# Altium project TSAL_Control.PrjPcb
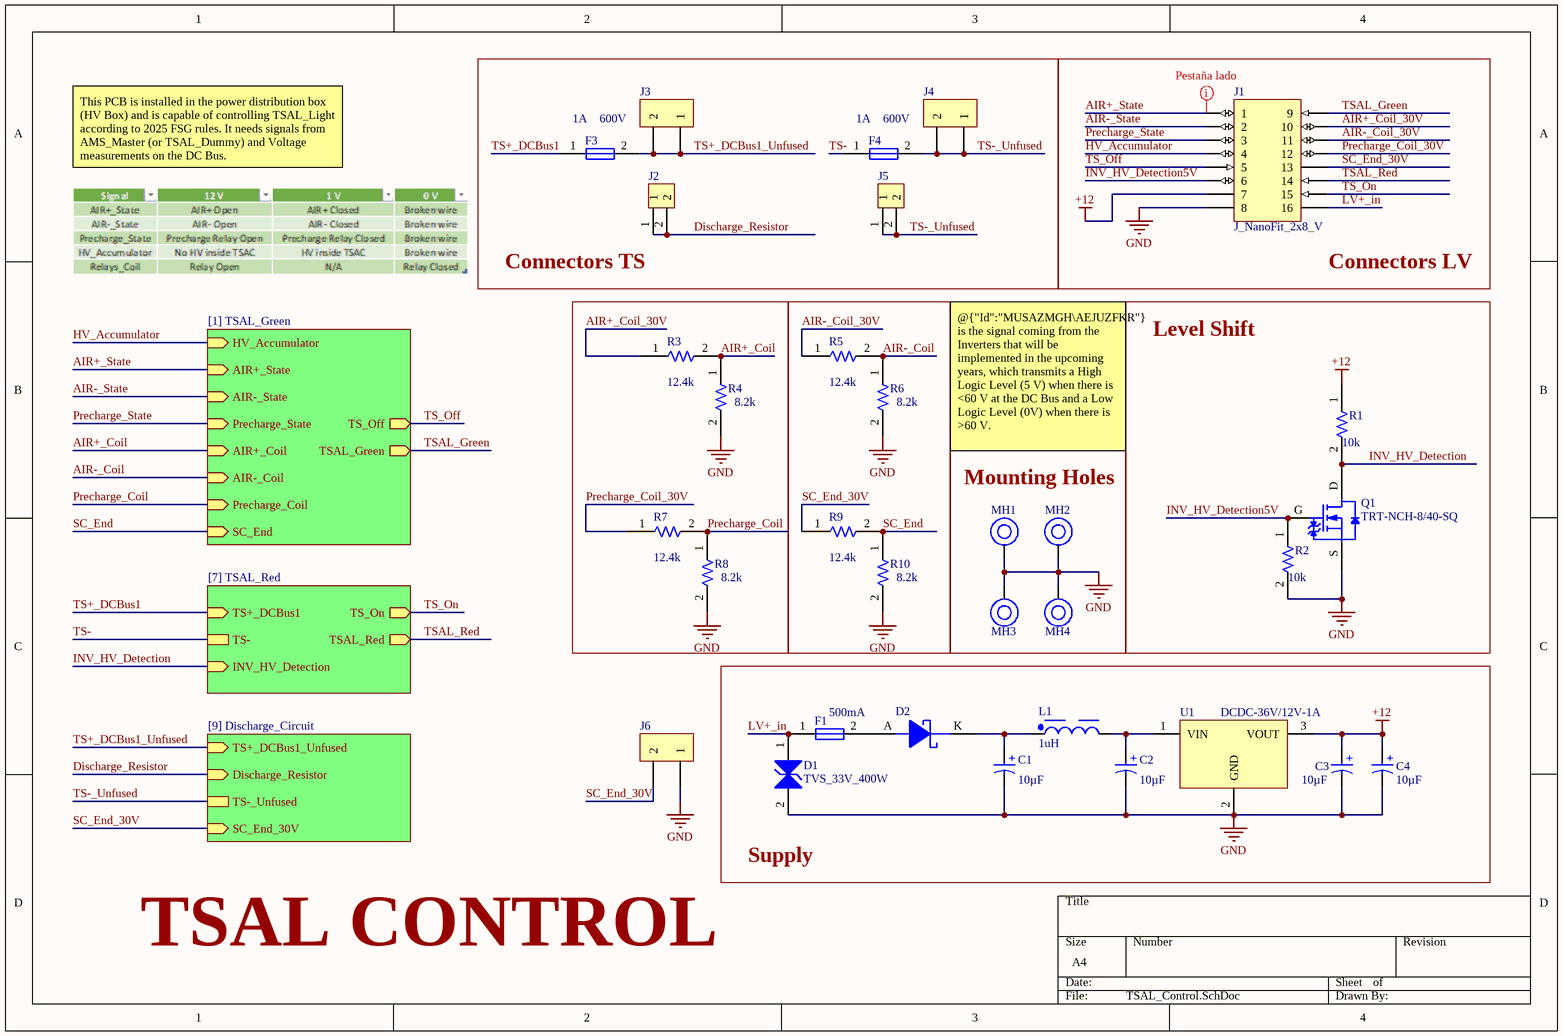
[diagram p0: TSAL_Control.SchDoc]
Company: e-Tech Racing; DesignedbyURL: e-techracing.es; DesignerMail: guillemroper@gmail.com; DesignerName: Guillem Ropero Serrano; Project: TSAL Control
10 sheets, 130 parts. Net scope: hierarchical (ports join the sheet entries above them; power ports are global).
Board file: TSAL_Control.PcbDoc
Sheets:
  TSAL_Control.SchDoc
    TSAL Green = [1] TSAL_Green.SchDoc
      Implausibilities = [2] Implausibilities.SchDoc
        Relay Implausibility = [3] Relay Implausibility.SchDoc
        SCS = [5] SCS.SchDoc
        EV 4.10.14 = [4] NoHV_RelaysClosed.SchDoc
      Green Driver = [6] Green_Driver.SchDoc
    TSAL Red = [7] TSAL_Red.SchDoc
      Red Driver = [8] Red_Driver.SchDoc
    Discharge_circuit = [9] Discharge_Circuit.SchDoc

## Sheet TSAL_Control.SchDoc
size A4; SheetNumber: 1; SheetTotal: 1; SPICEModelCacheMUSAZMGH: <root> / <DocumentId>MUSAZMGH</DocumentId> / </root>

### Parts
C1  value 10µF  [865080540004-Footprint-1]  (hidden comment: C10u-35V-Electrolytic)
C2  value 10µF  [865080540004-Footprint-1]  (hidden comment: C10u-35V-Electrolytic)
C3  value 10µF  [865080540004-Footprint-1]  (hidden comment: C10u-35V-Electrolytic)
C4  value 10µF  [865080540004-Footprint-1]  (hidden comment: C10u-35V-Electrolytic)
D1  TVS_33V_400W  [WE-TVSP_DO-214AC_Bidirectional]
D2  DSC-0.5/30-SOD123  [DSC-SOD123]  (value not drawn)
F1  Current Rating: 500mA  [0805]  (hidden comment: MFU0805FF00500P500)
F3  Current Rating: 1A  Voltage Rating (DC): 600V  [Fuse_485001]  (hidden comment: Fuse_1A_600V)
F4  Current Rating: 1A  Voltage Rating (DC): 600V  [Fuse_485001]  (hidden comment: Fuse_1A_600V)
J1  J_NanoFit_2x8_V  [J_NanoFit_2x8_V]
J2  J_MicroFit_2x1  [J_MicroFit_2x1]  (value not drawn)
J3  J_NanoFit_1x2  [FP-105309-1102-MFG]  (value not drawn)
J4  J_NanoFit_1x2  [FP-105309-1102-MFG]  (value not drawn)
J5  J_MicroFit_2x1  [J_MicroFit_2x1]  (value not drawn)
J6  J_NanoFit_1x2  [FP-105309-1102-MFG]  (value not drawn)
L1  value 1uH  [WE-PD2_4532]  (hidden comment: 7447730)
MH1  Mounting_Hole_M3  [Mounting_Hole_M3]  (value not drawn)
MH2  Mounting_Hole_M3  [Mounting_Hole_M3]  (value not drawn)
MH3  Mounting_Hole_M3  [Mounting_Hole_M3]  (value not drawn)
MH4  Mounting_Hole_M3  [Mounting_Hole_M3]  (value not drawn)
Q1  TRT-NCH-8/40-SQ  [TRT-NCH-3/35-CPH]
R1  value 10k  [R0805FTK]  (hidden comment: R10k-0805FTK)
R2  value 10k  [R0805FTK]  (hidden comment: R10k-0805FTK)
R3  value 12.4k  [0805]  (hidden comment: R12K4-0805-0.125W)
R4  value 8.2k  [0805]  (hidden comment: R8.2K_0805_0.125W)
R5  value 12.4k  [0805]  (hidden comment: R12K4-0805-0.125W)
R6  value 8.2k  [0805]  (hidden comment: R8.2K_0805_0.125W)
R7  value 12.4k  [0805]  (hidden comment: R12K4-0805-0.125W)
R8  value 8.2k  [0805]  (hidden comment: R8.2K_0805_0.125W)
R9  value 12.4k  [0805]  (hidden comment: R12K4-0805-0.125W)
R10  value 8.2k  [0805]  (hidden comment: R8.2K_0805_0.125W)
U1  DCDC-36V/12V-1A  [WPME-FDSM_SIP-3_L11.6W8H10.4]

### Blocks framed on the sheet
Connectors TS: F3 F4 J2-J5
Connectors LV: J1
Level Shift: Q1 R1 R2
Mounting Holes: MH1-MH4
Supply: C1-C4 D1 D2 F1 L1 U1

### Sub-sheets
Discharge_circuit = [9] Discharge_Circuit: Discharge_Resistor (in), SC_End_30V (in), TS-_Unfused, TS+_DCBus1_Unfused (in)
TSAL Green = [1] TSAL_Green: HV_Accumulator (in), AIR+_State (in), Precharge_State (in), AIR+_Coil (in), AIR-_Coil (in), Precharge_Coil (in), SC_End (in), TS_Off (out), TSAL_Green (out), AIR-_State (in)
TSAL Red = [7] TSAL_Red: TS+_DCBus1 (in), TS_On (out), INV_HV_Detection (in), TSAL_Red (out), TS-

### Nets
+12: C3.1(P) C4.1(P) J1.7 R1.1 U1.3(VOUT)
GND: C1.2(N) C2.2(N) C3.2(N) C4.2(N) D1.2 J1.8 J6.1 MH1.1 MH2.1 MH3.1 MH4.1 Q1.S R2.2 R4.2 R6.2 R8.2 R10.2 U1.2(GND)
AIR+_Coil: R3.2 R4.1 ; sheet TSAL Green/AIR+_Coil
AIR+_Coil_30V: J1.10 R3.1
AIR+_State: J1.1 ; sheet TSAL Green/AIR+_State
AIR-_Coil: R5.2 R6.1 ; sheet TSAL Green/AIR-_Coil
AIR-_Coil_30V: J1.11 R5.1
AIR-_State: J1.2 ; sheet TSAL Green/AIR-_State
Discharge_Resistor: J2.1 J2.2 ; sheet Discharge_circuit/Discharge_Resistor
HV_Accumulator: J1.4 ; sheet TSAL Green/HV_Accumulator
INV_HV_Detection: Q1.D R1.2 ; sheet TSAL Red/INV_HV_Detection
INV_HV_Detection5V: J1.6 Q1.G R2.1
LV+_in: D1.1 F1.1 J1.16
Precharge_Coil: R7.2 R8.1 ; sheet TSAL Green/Precharge_Coil
Precharge_Coil_30V: J1.12 R7.1
Precharge_State: J1.3 ; sheet TSAL Green/Precharge_State
SC_End: R9.2 R10.1 ; sheet TSAL Green/SC_End
SC_End_30V: J1.13 J6.2 R9.1 ; sheet Discharge_circuit/SC_End_30V
TS+_DCBus1: F3.1 ; sheet TSAL Red/TS+_DCBus1
TS+_DCBus1_Unfused: F3.2 J3.1 J3.2 ; sheet Discharge_circuit/TS+_DCBus1_Unfused
TS-: F4.1 ; sheet TSAL Red/TS-
TS-_Unfused: F4.2 J4.1 J4.2 J5.1 J5.2 ; sheet Discharge_circuit/TS-_Unfused
TS_Off: J1.5 ; sheet TSAL Green/TS_Off
TS_On: J1.15 ; sheet TSAL Red/TS_On
TSAL_Green: J1.9 ; sheet TSAL Green/TSAL_Green
TSAL_Red: J1.14 ; sheet TSAL Red/TSAL_Red
NetC1_1: C1.1(P) D2.K L1.1
NetC2_1: C2.1(P) L1.2 U1.1(VIN)
NetD2_A: D2.A F1.2

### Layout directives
mark named Pestaña lado: AIR+_State

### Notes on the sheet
- This PCB is installed in the power distribution box (HV Box) and is capable of controlling TSAL_Light according to 2025 FSG rules. It needs signals from AMS_Master (or TSAL_Dummy) and Voltage measurements on the DC Bus.
- @{"Id":"MUSAZMGH\AEJUZFKR"} is the signal coming from the Inverters that will be implemented in the upcoming years, which transmits a High Logic Level (5 V) when there is <60 V at the DC Bus and a Low Logic Level (0V) when there is >60 V.
- TSAL CONTROL

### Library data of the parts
C1-C4 = CMP-001-00019-3: WCAP-ASLI Aluminum Electrolytic Capacitors; Tolerance: 20%; Ripple Current (AC): 90mA; Voltage Rating: 35V
D1 = CMP-004-00003-1: Trans Voltage Suppressor Diode, 400W, Bidirectional, 1 Element, Silicon, DO-214AC
D2 = CMP-00165-2: VR=30V IF=500mA 30pF P=410mW; Max Reverse Leakage Current: 130uA; .Creator: GP; Max Reverse Voltage (DC): 30V; Element Configuration: Single; Average Rectified Current: 500mA; Peak Non-Repetitive Surge Current: 5.5A; Polarity: Standard; Forward Voltage: 430mV
F1 = CMP-001-00020-3: Fuse, 24 Milliohms to 660 Milliohms (Cold) @ 0.1, 32 V, 0805, 15 C, 35 C; Value: 0.5A-50V
F3 F4 = CMP-00161-2: Surface Mount Fuses 600V 1A Fast Acting; Manufacturer Part Number 1: 0485001.DR; Manufacturer 1: Littelfuse; .Creator: DO; Voltage Rating (AC): 250V; Approvals: UL,CSA; Fuse Type: Board Mount (Cartridge Style Excluded); Resistance: 0.264; DC Cold Resistance: 304.4mR; Body Material: Ceramic
J1 = CMP-00020-3: Nano-Fit Vertical Header Through Hole 2.50mm Pitch Dual Row 16 Circuits with Kinked Pins Tin (Sn) Plating Black; Manufacturer 1: Molex; Manufacturer Part Number 1: 105310-1116; Connector Type: Header,Male Pin; Number of Positions: 16; .Creator: AC
J2 J5 = CMP-00012-1: Header 1 Row Vertical Polarizing Peg 2 Pin SMT/Glow Wire Compatible Tin Plate; Manufacturer 1: Molex; Manufacturer Part Number 1: 43650-0215
J3 J4 J6 = CMP-002-00001-2: Conn HDR 2 POS 2.5mm Solder ST Thru-Hole 2 Terminal 1 Port Nano-Fit Tray
L1 = CMP-006-00005-1: General Purpose Inductor, 1uH, 20%, 1 Element, Nickel-zinc Ferrite-Core, SMD, 1816; Self Resonant Frequency: 110MHz; Max Current Rating: 4A
MH1-MH4 = CMP-00040-2
Q1 = CMP-00142-1: Automotive N-channel 40 V (d-s) 175C Mosfet SOT-23; Manufacturer Part Number 1: SQ2318BES-T1_GE3; Manufacturer 1: Vishay; Vds: 40V; .Creator: DO
R1 R2 = CMP-00085-4: BOURNS         CR0805-JW-103ELF            Surface Mount Chip Resistor, Thick Film, CR Series, 10 kohm, 125 mW,  5%, 150 V; Voltage Rating: 150V; Voltage Rating (DC): 100V; Max Power Dissipation: 125mW; Temperature Coefficient: 200ppm/°C; .Creator: DR
R3 R5 R7 R9 = CMP-009-00046-1: Fixed Resistor, Metal Glaze/thick Film, 0.125W, 12400ohm, 150V, 1% +/-Tol, 100ppm/Cel, Surface Mount, 0805; Power: 125mW
R4 R6 R8 R10 = CMP-009-00044-2: Fixed Resistor, Metal Glaze/thick Film, 0.125W, 8200ohm, 150V, 1% +/-Tol, 100ppm/Cel, Surface Mount, 0805; Power: 125mW
U1 = CMP-019-00006-1: Switching Regulator 36V In / 12 V Out, 1A. 173011235

## Sheet [1] TSAL_Green.SchDoc
size A4
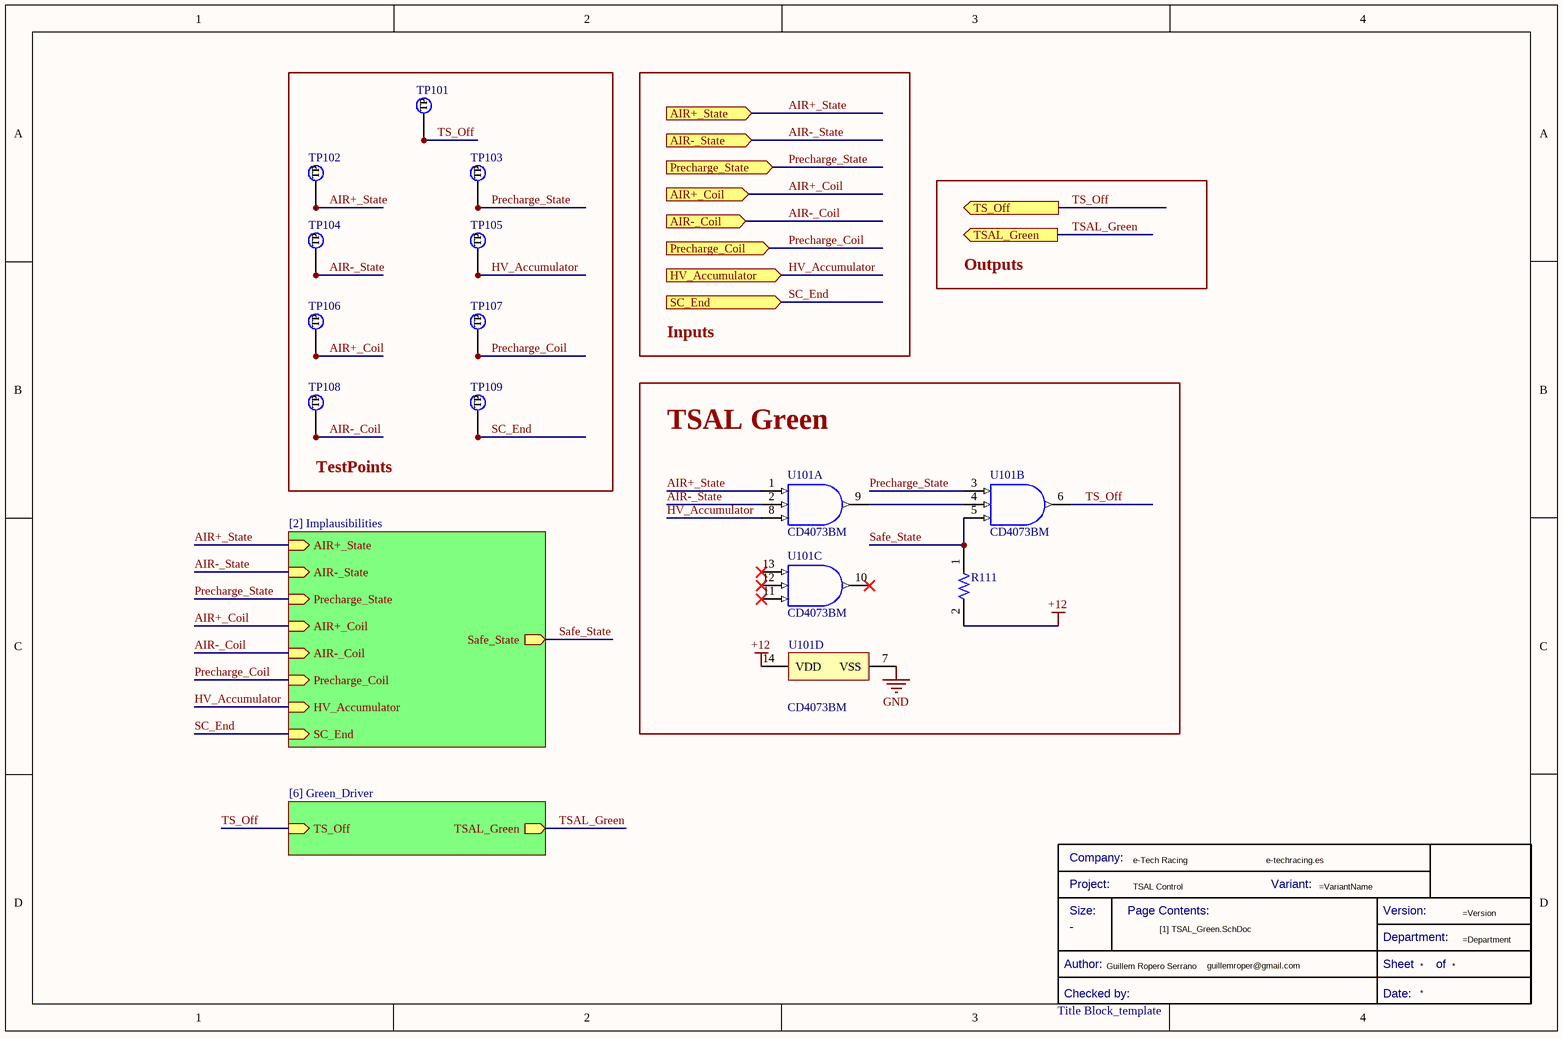
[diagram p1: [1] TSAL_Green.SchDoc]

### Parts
(Parts that share a designator on the sheet are numbered #1, #2 ... from top to bottom, then left to right.)
*#1  Title Block_template  (graphical)
R111  R470-0805FTK  [R0805FTK]  (value not drawn)
TP101  TestPoint  [TestPoint]  (value not drawn)  (no BOM)
TP102  TestPoint  [TestPoint]  (value not drawn)  (no BOM)
TP103  TestPoint  [TestPoint]  (value not drawn)  (no BOM)
TP104  TestPoint  [TestPoint]  (value not drawn)  (no BOM)
TP105  TestPoint  [TestPoint]  (value not drawn)  (no BOM)
TP106  TestPoint  [TestPoint]  (value not drawn)  (no BOM)
TP107  TestPoint  [TestPoint]  (value not drawn)  (no BOM)
TP108  TestPoint  [TestPoint]  (value not drawn)  (no BOM)
TP109  TestPoint  [TestPoint]  (value not drawn)  (no BOM)
U101  CD4073BM  [D0014A_N]  (parts A,B,C,D of 4)

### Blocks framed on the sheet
TestPoints: TP101-TP109
TSAL Green: R111 U101

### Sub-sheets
Green Driver = [6] Green_Driver: TS_Off (in), TSAL_Green (out)
Implausibilities = [2] Implausibilities: AIR+_State (in), Precharge_State (in), AIR+_Coil (in), AIR-_Coil (in), Precharge_Coil (in), HV_Accumulator (in), Safe_State (out), SC_End (in), AIR-_State (in)

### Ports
AIR+_Coil (in, see TSAL_Control[1B], [2] Implausibilities[1A], [3] Relay Implausibility[1A], [4] NoHV_RelaysClosed[1A]), AIR+_State (in, see TSAL_Control[1B], [2] Implausibilities[1A], [3] Relay Implausibility[1A], [5] SCS[1A]), AIR-_Coil (in, see TSAL_Control[1B], [2] Implausibilities[1A], [3] Relay Implausibility[1A], [4] NoHV_RelaysClosed[1A]), AIR-_State (in, see TSAL_Control[1B], [2] Implausibilities[1A], [3] Relay Implausibility[1A], [5] SCS[1A]), HV_Accumulator (in, see TSAL_Control[1B], [2] Implausibilities[1A], [4] NoHV_RelaysClosed[1A], [5] SCS[1A]), Precharge_Coil (in, see TSAL_Control[1C], [2] Implausibilities[1A], [3] Relay Implausibility[1A], [4] NoHV_RelaysClosed[1A]), Precharge_State (in, see TSAL_Control[1B], [2] Implausibilities[1A], [3] Relay Implausibility[1A], [5] SCS[1A]), SC_End (in, see TSAL_Control[1C], [2] Implausibilities[1A], [3] Relay Implausibility[1B], [4] NoHV_RelaysClosed[1A]), TS_Off (out, see TSAL_Control[2B], [6] Green_Driver[1A]), TSAL_Green (out, see TSAL_Control[2B], [6] Green_Driver[2A])

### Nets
+12: R111.2 U101.14(VDD)
GND: U101.7(VSS)
AIR+_Coil: TP106.1(TP) ; port AIR+_Coil, sheet Implausibilities/AIR+_Coil
AIR+_State: TP102.1(TP) U101.1(A) ; port AIR+_State, sheet Implausibilities/AIR+_State
AIR-_Coil: TP108.1(TP) ; port AIR-_Coil, sheet Implausibilities/AIR-_Coil
AIR-_State: TP104.1(TP) U101.2(B) ; port AIR-_State, sheet Implausibilities/AIR-_State
HV_Accumulator: TP105.1(TP) U101.8(C) ; port HV_Accumulator, sheet Implausibilities/HV_Accumulator
Precharge_Coil: TP107.1(TP) ; port Precharge_Coil, sheet Implausibilities/Precharge_Coil
Precharge_State: TP103.1(TP) U101.3(D) ; port Precharge_State, sheet Implausibilities/Precharge_State
Safe_State: R111.1 U101.5(F) ; sheet Implausibilities/Safe_State
SC_End: TP109.1(TP) ; port SC_End, sheet Implausibilities/SC_End
TS_Off: TP101.1(TP) U101.6(K) ; port TS_Off, sheet Green Driver/TS_Off
TSAL_Green: port TSAL_Green, sheet Green Driver/TSAL_Green
NetU101_4: U101.4(E) U101.9(J)

Not connected (* = marked no-connect by the designer): U101 10(L)* 11(I)* 12(H)* 13(G)*

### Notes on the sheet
- Outputs
- Inputs

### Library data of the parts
*#1 = CMP-00043-7: Standard Title Block; .Creator: GP
R111 = CMP-00093-2: Res Thick Film 0805 470 Ohm 1% 1/8W ±100ppm/°C Molded SMD SMD Paper Tape on Plastic Reel; Manufacturer Part Number 1: CR0805-FX-4700GLF; Manufacturer 1: Bourns; Power Rating: 125mW; Voltage Rating (DC): 150V; .Creator: DR; Value: 470
TP101-TP109 = CMP-00042-1: Test Point 1x1 mm; .SCHcheck: GP
U101 = CMP-00213-1: AND Gate, 4000/14000/40000 Series, 3-Func, 3-Input, CMOS, PDSO14; Propagation Delay (tpd): 250ns; Nominal Supply Voltage: 5V; Power Supplies: 5/15V; Qualification Status: Not Qualified; Package Equivalence Code: SOP14,.25; Channels: 3; Min Supply Voltage: 3V; Package Body Material: Plastic; Max Supply Voltage: 18V; Load Capacitance (CL): 50pF; Load/Preset Input: Yes; Schmitt Trigger: No

## Sheet [2] Implausibilities.SchDoc
size A4
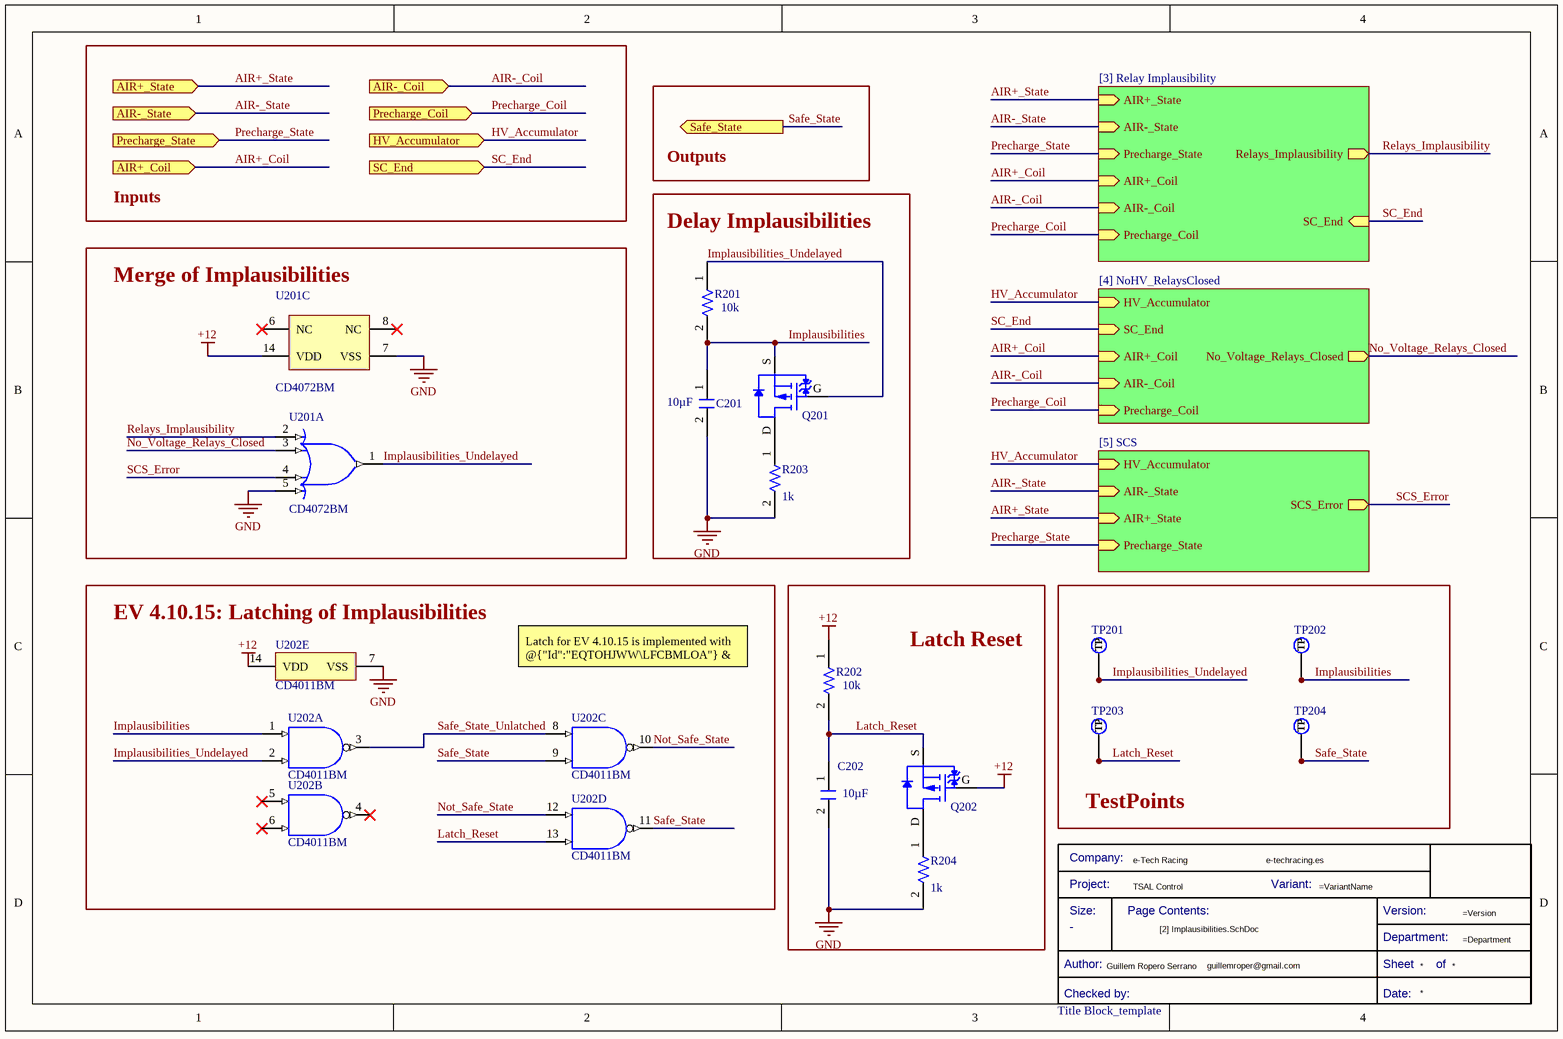
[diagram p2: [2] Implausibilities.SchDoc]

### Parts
(Parts that share a designator on the sheet are numbered #1, #2 ... from top to bottom, then left to right.)
*#2  Title Block_template  (graphical)
C201  value 10µF  [C0805FNPC-R]  (hidden comment: C10u-16V-0805FNPC-X5R)
C202  value 10µF  [C0805FNPC-R]  (hidden comment: C10u-16V-0805FNPC-X5R)
Q201  TRT-PCH-2/30-BSS  [TRT-PCH-2/30-BSS]  (value not drawn)
Q202  TRT-PCH-2/30-BSS  [TRT-PCH-2/30-BSS]  (value not drawn)
R201  value 10k  [R0805FTK]  (hidden comment: R10k-0805FTK)
R202  value 10k  [R0805FTK]  (hidden comment: R10k-0805FTK)
R203  value 1k  [0805]  (hidden comment: R1K-0805-0.5W)
R204  value 1k  [0805]  (hidden comment: R1K-0805-0.5W)
TP201  TestPoint  [TestPoint]  (value not drawn)  (no BOM)
TP202  TestPoint  [TestPoint]  (value not drawn)  (no BOM)
TP203  TestPoint  [TestPoint]  (value not drawn)  (no BOM)
TP204  TestPoint  [TestPoint]  (value not drawn)  (no BOM)
U201  CD4072BM  [D0014A_N]  (parts A,C of 3)
U202  CD4011BM  [D0014A_N]  (parts A,B,C,D,E of 5)

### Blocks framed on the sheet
Delay Implausibilities: C201 Q201 R201 R203
Merge of Implausibilities: U201
EV 4.10.15: Latching of Implausibilities: U202
Latch Reset: C202 Q202 R202 R204
TestPoints: TP201-TP204

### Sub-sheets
EV 4.10.14 = [4] NoHV_RelaysClosed: HV_Accumulator (in), SC_End (in), AIR+_Coil (in), AIR-_Coil (in), Precharge_Coil (in), No_Voltage_Relays_Closed (out)
Relay Implausibility = [3] Relay Implausibility: AIR+_State (in), Precharge_State (in), AIR+_Coil (in), AIR-_Coil (in), Precharge_Coil (in), Relays_Implausibility (out), SC_End (in), AIR-_State (in)
SCS = [5] SCS: HV_Accumulator (in), AIR-_State (in), Precharge_State (in), SCS_Error (out), AIR+_State (in)

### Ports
AIR+_Coil (in, see [1] TSAL_Green[1C], [1] TSAL_Green[2A], [3] Relay Implausibility[1A], [4] NoHV_RelaysClosed[1A]), AIR+_State (in, see [1] TSAL_Green[1C], [1] TSAL_Green[2A], [3] Relay Implausibility[1A], [5] SCS[1A]), AIR-_Coil (in, see [1] TSAL_Green[1C], [1] TSAL_Green[2A], [3] Relay Implausibility[1A], [4] NoHV_RelaysClosed[1A]), AIR-_State (in, see [1] TSAL_Green[1C], [1] TSAL_Green[2A], [3] Relay Implausibility[1A], [5] SCS[1A]), HV_Accumulator (in, see [1] TSAL_Green[1C], [1] TSAL_Green[2B], [4] NoHV_RelaysClosed[1A], [5] SCS[1A]), Precharge_Coil (in, see [1] TSAL_Green[1C], [1] TSAL_Green[2A], [3] Relay Implausibility[1A], [4] NoHV_RelaysClosed[1A]), Precharge_State (in, see [1] TSAL_Green[1C], [1] TSAL_Green[2A], [3] Relay Implausibility[1A], [5] SCS[1A]), Safe_State (out, see [1] TSAL_Green[2C]), SC_End (in, see [1] TSAL_Green[1C], [1] TSAL_Green[2B], [3] Relay Implausibility[1B], [4] NoHV_RelaysClosed[1A])

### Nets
+12: Q202.G R202.1 U201.14(VDD) U202.14(VDD)
GND: C201.2 C202.2 R203.2 R204.2 U201.5(D) U201.7(VSS) U202.7(VSS)
AIR+_Coil: port AIR+_Coil, sheet Relay Implausibility/AIR+_Coil, sheet EV 4.10.14/AIR+_Coil
AIR+_State: port AIR+_State, sheet Relay Implausibility/AIR+_State, sheet SCS/AIR+_State
AIR-_Coil: port AIR-_Coil, sheet Relay Implausibility/AIR-_Coil, sheet EV 4.10.14/AIR-_Coil
AIR-_State: port AIR-_State, sheet Relay Implausibility/AIR-_State, sheet SCS/AIR-_State
HV_Accumulator: port HV_Accumulator, sheet SCS/HV_Accumulator, sheet EV 4.10.14/HV_Accumulator
Implausibilities: C201.1 Q201.S R201.2 TP202.1(TP) U202.1(A)
Implausibilities_Undelayed: Q201.G R201.1 TP201.1(TP) U201.1(J) U202.2(B)
Latch_Reset: C202.1 Q202.S R202.2 TP203.1(TP) U202.13(H)
No_Voltage_Relays_Closed: U201.3(B) ; sheet EV 4.10.14/No_Voltage_Relays_Closed
Not_Safe_State: U202.10(L) U202.12(G)
Precharge_Coil: port Precharge_Coil, sheet Relay Implausibility/Precharge_Coil, sheet EV 4.10.14/Precharge_Coil
Precharge_State: port Precharge_State, sheet Relay Implausibility/Precharge_State, sheet SCS/Precharge_State
Relays_Implausibility: U201.2(A) ; sheet Relay Implausibility/Relays_Implausibility
Safe_State: TP204.1(TP) U202.9(F) U202.11(M) ; port Safe_State
Safe_State_Unlatched: U202.3(J) U202.8(E)
SC_End: port SC_End, sheet Relay Implausibility/SC_End, sheet EV 4.10.14/SC_End
SCS_Error: U201.4(C) ; sheet SCS/SCS_Error
NetQ201_D: Q201.D R203.1
NetQ202_D: Q202.D R204.1

Not connected (* = marked no-connect by the designer): U201 6(NC)* 8(NC)*; U202 4(K)* 5(C)* 6(D)*

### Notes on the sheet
- Outputs
- Inputs
- Latch for EV 4.10.15 is implemented with @{"Id":"EQTOHJWW\LFCBMLOA"} & @{"Id":"EQTOHJWW\TXFEAGDM"}

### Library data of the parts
*#2 = CMP-00043-7: Standard Title Block; .Creator: GP
C201 C202 = CMP-00055-8: Multilayer Ceramic Capacitor, Wcap-Csgp Series, 10 F, 20%, X5R, 16 V, 0805 [2012 Metric] Rohs Compliant: Yes; Manufacturer Part Number 1: 885012107014; Manufacturer 1: Wurth Electronics; .Creator: DR; Voltage Rating: 16V
Q201 Q202 = CMP-00144-2: Infineon’s highly innovative OptiMOS™ families include p-channel power MOSFETs, SOT-23-3, RoHS; Manufacturer Part Number: BSS308PEH6327; .Creator: DO; Drain to Source Voltage (Vdss): 30V; Rise Time: 7.7ns; Turn-On Delay Time: 5.6ns; Fall Time: 2.8ns; Input Capacitance: 500pF; Turn-Off Delay Time: 15.3ns; Rds On Max: 80mR; Threshold Voltage: -1.5V; Gate to Source Voltage (Vgs): 20V; Max Power Dissipation: 500mW; Continuous Drain Current (ID): 2A
R201 R202 = CMP-00085-4: BOURNS         CR0805-JW-103ELF            Surface Mount Chip Resistor, Thick Film, CR Series, 10 kohm, 125 mW,  5%, 150 V; .Creator: DR; Power Rating: 125mW; Voltage Rating (DC): 100V; Voltage Rating: 150V; Temperature Coefficient: 200ppm/°C
R203 R204 = CMP-009-00043-2: Fixed Resistor, Metal Glaze/thick Film, 0.5W, 1000ohm, 150V, 1% +/-Tol, 100ppm/Cel, Surface Mount, 0805; Power: 500mW
TP201-TP204 = CMP-00042-1: Test Point 1x1 mm; .SCHcheck: GP
U201 = CMP-00217-1: OR Gate, 4000/14000/40000 Series, 2-Func, 4-Input, CMOS, PDSO14; Package Equivalence Code: SOP14,.25; Package Body Material: Plastic; Power Supplies: 5/15V; Schmitt Trigger: No; Propagation Delay (tpd): 250ns; Nominal Supply Voltage: 5V; Min Supply Voltage: 3V; Channels: 2; Output Characteristics: OPEN-COLLECTOR; Max Supply Voltage: 18V; Load Capacitance (CL): 50pF; Logic Type: OR GATE; Qualification Status: Not Qualified; Number of Inputs: 4
U202 = CMP-00211-1: NAND Gate, 4000/14000/40000 Series, 4-Func, 2-Input, CMOS, PDSO14; Package Equivalence Code: SOP14,.25; Package Body Material: Plastic; Load Capacitance (CL): 50pF; Max Supply Voltage: 18V; Min Supply Voltage: 3V; Nominal Supply Voltage: 5V; Propagation Delay (tpd): 250ns; Number of Inputs: 2; Channels: 4; Qualification Status: Not Qualified; Load/Preset Input: Yes; Schmitt Trigger: No; Power Supplies: 5/15V

## Sheet [3] Relay Implausibility.SchDoc
size A4
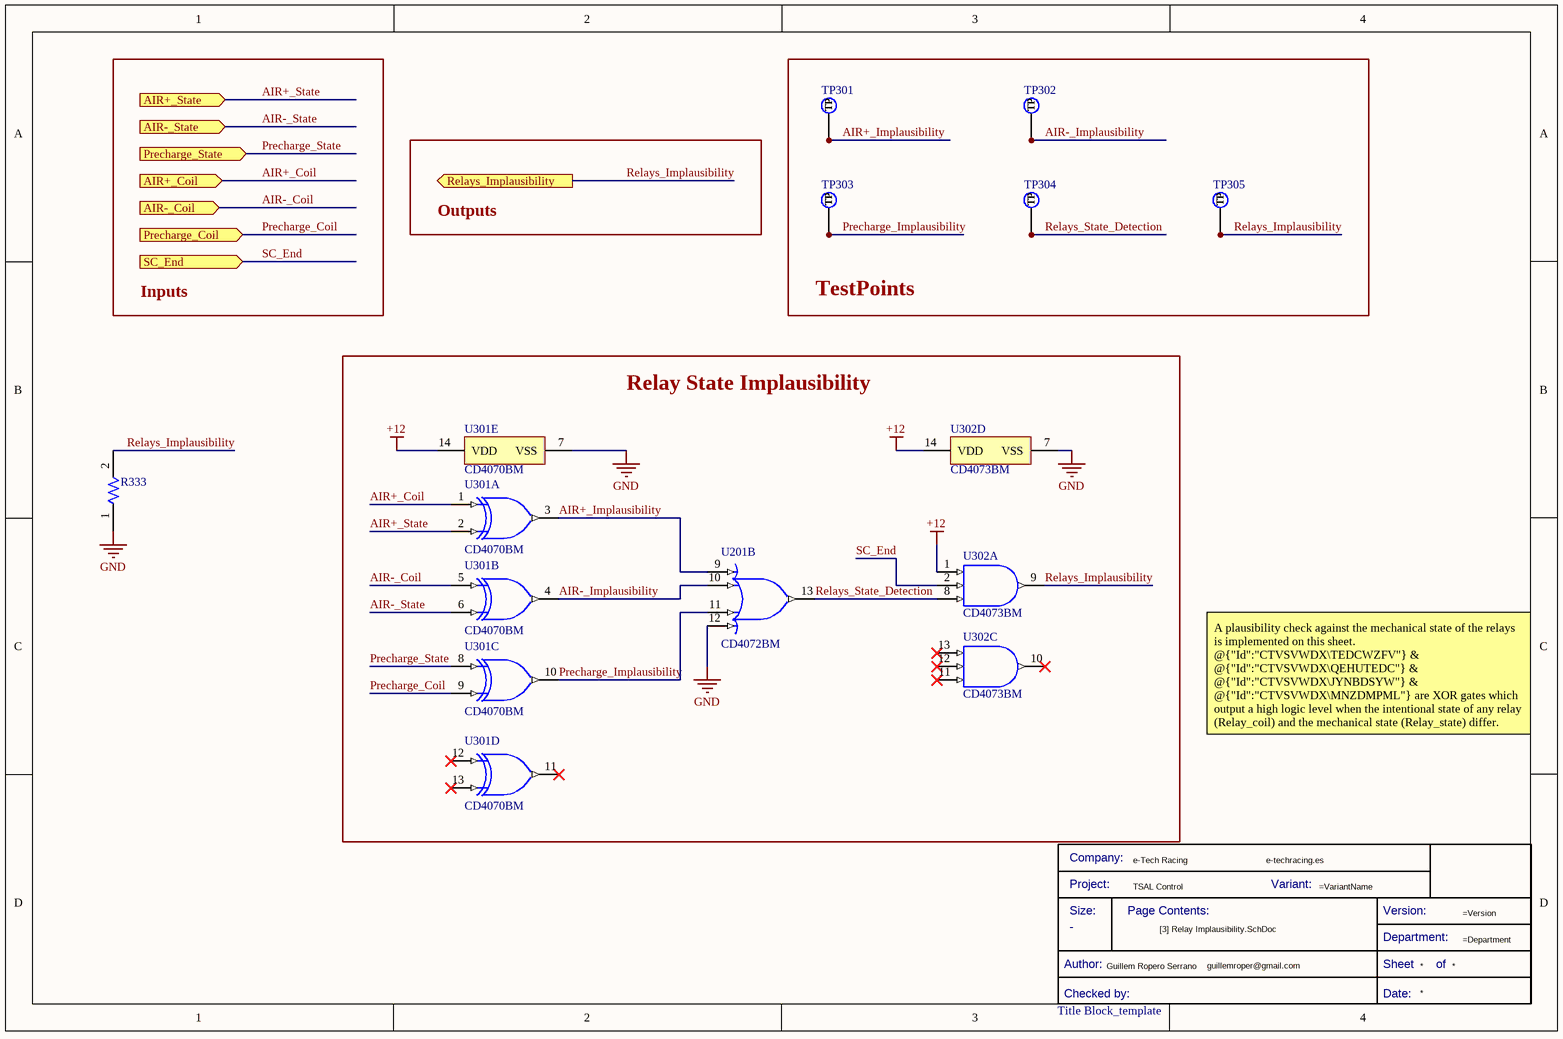
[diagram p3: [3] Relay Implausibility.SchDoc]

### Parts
(Parts that share a designator on the sheet are numbered #1, #2 ... from top to bottom, then left to right.)
*#3  Title Block_template  (graphical)
R333  R470-0805FTK  [R0805FTK]  (value not drawn)
TP301  TestPoint  [TestPoint]  (value not drawn)  (no BOM)
TP302  TestPoint  [TestPoint]  (value not drawn)  (no BOM)
TP303  TestPoint  [TestPoint]  (value not drawn)  (no BOM)
TP304  TestPoint  [TestPoint]  (value not drawn)  (no BOM)
TP305  TestPoint  [TestPoint]  (value not drawn)  (no BOM)
U201  CD4072BM  [D0014A_N]  (part B of 3)
U301  CD4070BM  [D0014A_N]  (parts A,B,C,D,E of 5)
U302  CD4073BM  [D0014A_N]  (parts A,C,D of 4)

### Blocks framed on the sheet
TestPoints: TP301-TP305
Relay State Implausibility: U201 U301 U302

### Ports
AIR+_Coil (in, see [2] Implausibilities[3A], [1] TSAL_Green[2A], [2] Implausibilities[1A], [4] NoHV_RelaysClosed[1A]), AIR+_State (in, see [2] Implausibilities[3A], [1] TSAL_Green[2A], [2] Implausibilities[1A], [5] SCS[1A]), AIR-_Coil (in, see [2] Implausibilities[3A], [1] TSAL_Green[2A], [2] Implausibilities[1A], [4] NoHV_RelaysClosed[1A]), AIR-_State (in, see [2] Implausibilities[3A], [1] TSAL_Green[2A], [2] Implausibilities[1A], [5] SCS[1A]), Precharge_Coil (in, see [2] Implausibilities[3A], [1] TSAL_Green[2A], [2] Implausibilities[1A], [4] NoHV_RelaysClosed[1A]), Precharge_State (in, see [2] Implausibilities[3A], [1] TSAL_Green[2A], [2] Implausibilities[1A], [5] SCS[1A]), Relays_Implausibility (out, see [2] Implausibilities[4A]), SC_End (in, see [2] Implausibilities[4A], [1] TSAL_Green[2B], [2] Implausibilities[1A], [4] NoHV_RelaysClosed[1A])

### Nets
+12: U301.14(VDD) U302.1(A) U302.14(VDD)
GND: R333.1 U201.12(H) U301.7(VSS) U302.7(VSS)
AIR+_Coil: U301.1(A) ; port AIR+_Coil
AIR+_Implausibility: TP301.1(TP) U201.9(E) U301.3(J)
AIR+_State: U301.2(B) ; port AIR+_State
AIR-_Coil: U301.5(C) ; port AIR-_Coil
AIR-_Implausibility: TP302.1(TP) U201.10(F) U301.4(K)
AIR-_State: U301.6(D) ; port AIR-_State
Precharge_Coil: U301.9(F) ; port Precharge_Coil
Precharge_Implausibility: TP303.1(TP) U201.11(G) U301.10(L)
Precharge_State: U301.8(E) ; port Precharge_State
Relays_Implausibility: R333.2 TP305.1(TP) U302.9(J) ; port Relays_Implausibility
Relays_State_Detection: TP304.1(TP) U201.13(K) U302.8(C)
SC_End: U302.2(B) ; port SC_End

Not connected (* = marked no-connect by the designer): U301 11(M)* 12(G)* 13(H)*; U302 10(L)* 11(I)* 12(H)* 13(G)*

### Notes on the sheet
- Outputs
- Inputs
- A plausibility check against the mechanical state of the relays is implemented on this sheet. @{"Id":"CTVSVWDX\TEDCWZFV"} & @{"Id":"CTVSVWDX\QEHUTEDC"} & @{"Id":"CTVSVWDX\JYNBDSYW"} & @{"Id":"CTVSVWDX\MNZDMPML"} are XOR gates which output a high logic level when the intentional state of any relay (Relay_coil) and the mechanical state (Relay_state) differ.
  As the Relay's Coil inside the TSAC are supplied directly from the Shutdown Chain, the @{"Id":"CTVSVWDX\UYTFIWRP"} conditions the implausibility detection to the SC to be closed.

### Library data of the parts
*#3 = CMP-00043-7: Standard Title Block; .Creator: GP
R333 = CMP-00093-2: as R111 on sheet [1] TSAL_Green
TP301-TP305 = CMP-00042-1: Test Point 1x1 mm; .SCHcheck: GP
U201 = CMP-00217-1: as U201 on sheet [2] Implausibilities
U301 = CMP-00216-1: XOR Gate, 4000/14000/40000 Series, 4-Func, 2-Input, CMOS, PDSO14; Package Equivalence Code: SOP14,.25; Number of Inputs: 2; Nominal Supply Voltage: 5V; Qualification Status: Not Qualified; Max Supply Voltage: 18V; Channels: 4; Min Supply Voltage: 3V; Prop. Delay@Nom-Sup: 280ns; Package Body Material: Plastic; Schmitt Trigger: No; Load Capacitance (CL): 50pF; Power Supplies: 5/15V
U302 = CMP-00213-1: as U101 on sheet [1] TSAL_Green

## Sheet [5] SCS.SchDoc
size A4
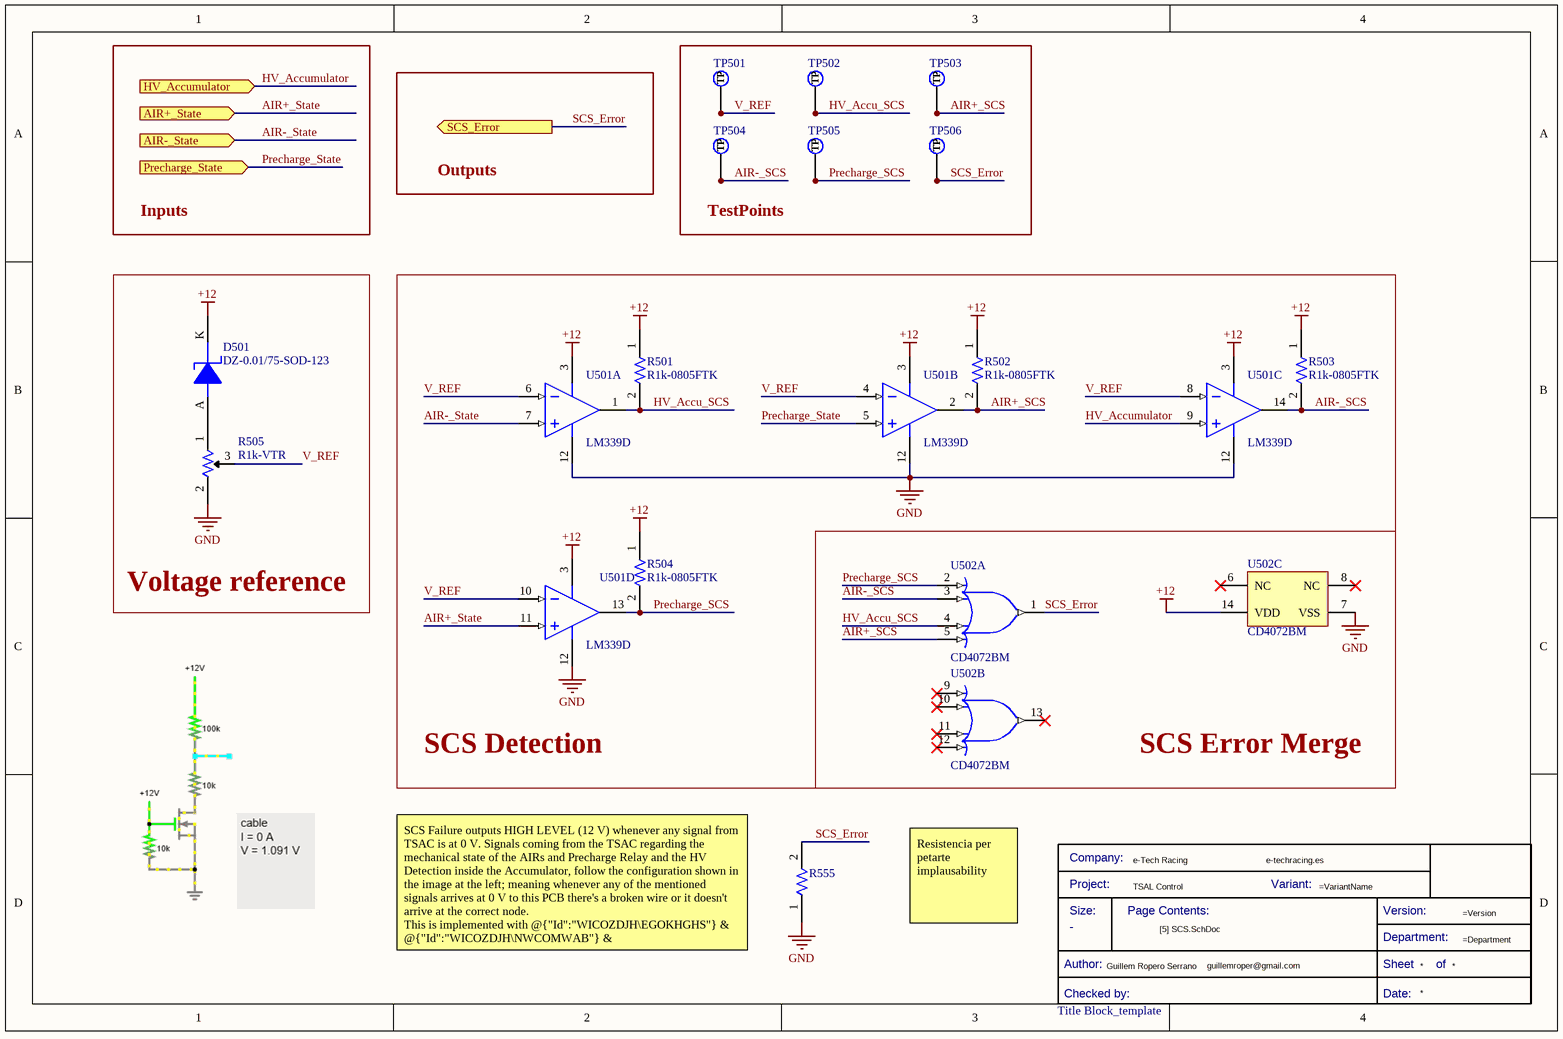
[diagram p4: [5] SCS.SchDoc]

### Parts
(Parts that share a designator on the sheet are numbered #1, #2 ... from top to bottom, then left to right.)
*#4  Title Block_template  (graphical)
D501  DZ-0.01/75-SOD-123  [DSC-SOD123]
R501  R1k-0805FTK  [R0805FTK]
R502  R1k-0805FTK  [R0805FTK]
R503  R1k-0805FTK  [R0805FTK]
R504  R1k-0805FTK  [R0805FTK]
R505  R1k-VTR  [R1k-VTR]
R555  R470-0805FTK  [R0805FTK]  (value not drawn)
TP501  TestPoint  [TestPoint]  (value not drawn)  (no BOM)
TP502  TestPoint  [TestPoint]  (value not drawn)  (no BOM)
TP503  TestPoint  [TestPoint]  (value not drawn)  (no BOM)
TP504  TestPoint  [TestPoint]  (value not drawn)  (no BOM)
TP505  TestPoint  [TestPoint]  (value not drawn)  (no BOM)
TP506  TestPoint  [TestPoint]  (value not drawn)  (no BOM)
U501  LM339D  [D0014A_N]  (parts A,B,C,D of 4)
U502  CD4072BM  [D0014A_N]  (parts A,B,C of 3)

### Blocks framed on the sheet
TestPoints: TP501-TP506
Voltage reference: D501 R505
SCS Detection: R501-R504 U501
SCS Error Merge: U502

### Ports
AIR+_State (in, see [2] Implausibilities[3C], [1] TSAL_Green[2A], [2] Implausibilities[1A], [3] Relay Implausibility[1A]), AIR-_State (in, see [2] Implausibilities[3B], [1] TSAL_Green[2A], [2] Implausibilities[1A], [3] Relay Implausibility[1A]), HV_Accumulator (in, see [2] Implausibilities[3B], [1] TSAL_Green[2B], [2] Implausibilities[1A], [4] NoHV_RelaysClosed[1A]), Precharge_State (in, see [2] Implausibilities[3C], [1] TSAL_Green[2A], [2] Implausibilities[1A], [3] Relay Implausibility[1A]), SCS_Error (out, see [2] Implausibilities[4B])

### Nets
+12: D501.K R501.1 R502.1 R503.1 R504.1 U501.3(VCC) U502.14(VDD)
GND: R505.2 R555.1 U501.12(GND) U502.7(VSS)
AIR+_SCS: R502.2 TP503.1(TP) U501.2(OUT2) U502.5(D)
AIR+_State: U501.11(IN4+) ; port AIR+_State
AIR-_SCS: R503.2 TP504.1(TP) U501.14(OUT3) U502.3(B)
AIR-_State: U501.7(IN1+) ; port AIR-_State
HV_Accu_SCS: R501.2 TP502.1(TP) U501.1(OUT1) U502.4(C)
HV_Accumulator: U501.9(IN3+) ; port HV_Accumulator
Precharge_SCS: R504.2 TP505.1(TP) U501.13(OUT4) U502.2(A)
Precharge_State: U501.5(IN2+) ; port Precharge_State
SCS_Error: R555.2 TP506.1(TP) U502.1(J) ; port SCS_Error
V_REF: R505.3 TP501.1(TP) U501.4(IN2-) U501.6(IN1-) U501.8(IN3-) U501.10(IN4-)
NetD501_A: D501.A R505.1

Not connected (* = marked no-connect by the designer): U502 6(NC)* 8(NC)* 9(E)* 10(F)* 11(G)* 12(H)* 13(K)*

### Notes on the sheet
- Outputs
- Inputs
- Resistencia per petarte implausability
- SCS Failure outputs HIGH LEVEL (12 V) whenever any signal from TSAC is at 0 V. Signals coming from the TSAC regarding the mechanical state of the AIRs and Precharge Relay and the HV Detection inside the Accumulator, follow the configuration shown in the image at the left; meaning whenever any of the mentioned signals arrives at 0 V to this PCB there's a broken wire or it doesn't arrive at the correct node.
  This is implemented with @{"Id":"WICOZDJH\EGOKHGHS"} & @{"Id":"WICOZDJH\NWCOMWAB"} & @{"Id":"WICOZDJH\OSDIWEFW"} & @{"Id":"WICOZDJH\TEKHYVMJ"}.

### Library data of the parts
*#4 = CMP-00043-7: Standard Title Block; .Creator: GP
D501 = CMP-00159-1: Diode Zener Single 10V 2% 500mW 2-Pin SOD-123 T/R; Manufacturer Part Number: MMSZ5240C-HE3-08; Manufacturer: Vishay; .Creator: DO; Max Reverse Leakage Current: 3uA; Impedance: 17R; Zener Current: 20mA
R501-R504 = CMP-00076-2: Res Thick Film 0805 1K Ohm 5% 1/8W ±200ppm/°C Molded SMD SMD Paper Tape on Plastic Reel; Manufacturer Part Number 1: CR0805-JW-102ELF; Manufacturer 1: Bourns; Voltage Rating (DC): 150V; Power Rating: 125mW; .Creator: GP
R505 = CMP-00071-1: Res Cermet Trimmer 1K Ohm 10% 1/2W 25(Elec)Turn 2.19mm (9.53 X 4.83 X 11.55mm) Pin Thru-Hole Tube; Manufacturer Part Number: 3296Y-1-102LF; Manufacturer: Bourns; Number of Turns: 25; Temperature Coefficient: 100ppm/°C; .Creator: DO; Max Power Dissipation: 500mW
R555 = CMP-00093-2: as R111 on sheet [1] TSAL_Green
TP501-TP506 = CMP-00042-1: Test Point 1x1 mm; .SCHcheck: GP
U501 = CMP-014-00006-1: Comparator, 4 Func, 5000uV Offset-Max, 300ns Response Time, BIPolar, PDSO14; Nominal Supply Voltage: 5V; Channels: 4; Output Type: OPEN-COLLECTOR
U502 = CMP-00217-1: as U201 on sheet [2] Implausibilities

## Sheet [4] NoHV_RelaysClosed.SchDoc
size A4
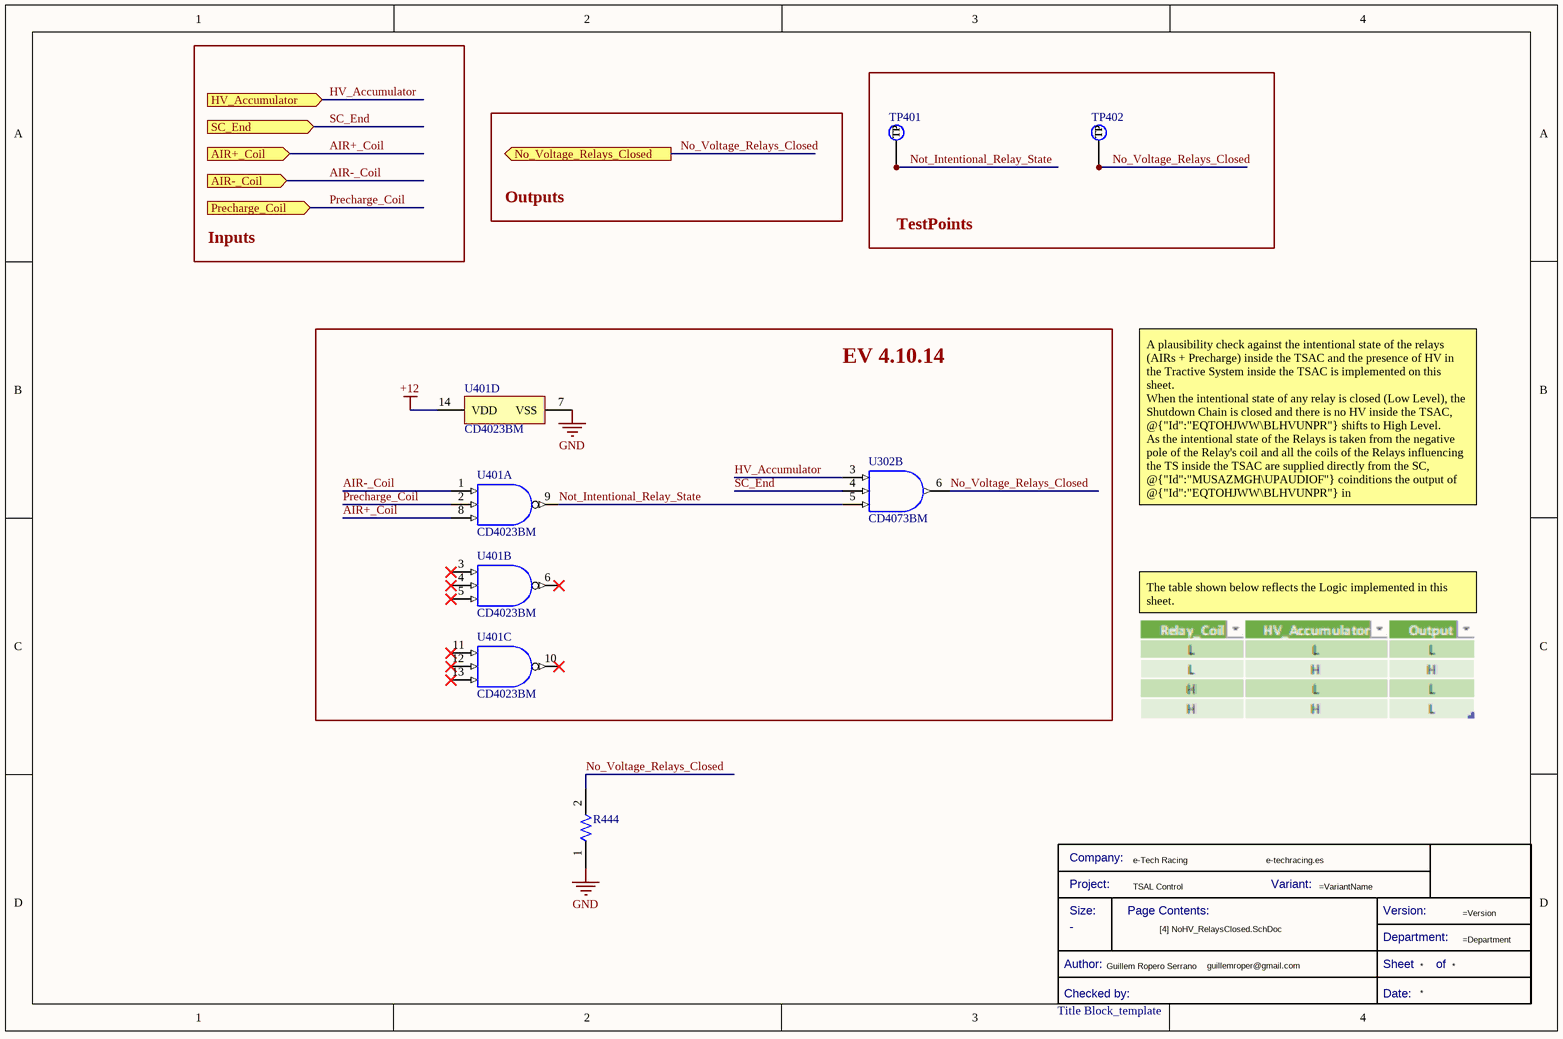
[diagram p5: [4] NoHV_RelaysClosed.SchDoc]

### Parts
(Parts that share a designator on the sheet are numbered #1, #2 ... from top to bottom, then left to right.)
*#5  Title Block_template  (graphical)
R444  R470-0805FTK  [R0805FTK]  (value not drawn)
TP401  TestPoint  [TestPoint]  (value not drawn)  (no BOM)
TP402  TestPoint  [TestPoint]  (value not drawn)  (no BOM)
U302  CD4073BM  [D0014A_N]  (part B of 4)
U401  CD4023BM  [D0014A_N]  (parts A,B,C,D of 4)

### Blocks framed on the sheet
TestPoints: TP401 TP402
EV 4.10.14: U302 U401

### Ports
AIR+_Coil (in, see [2] Implausibilities[3B], [1] TSAL_Green[2A], [2] Implausibilities[1A], [3] Relay Implausibility[1A]), AIR-_Coil (in, see [2] Implausibilities[3B], [1] TSAL_Green[2A], [2] Implausibilities[1A], [3] Relay Implausibility[1A]), HV_Accumulator (in, see [2] Implausibilities[3B], [1] TSAL_Green[2B], [2] Implausibilities[1A], [5] SCS[1A]), No_Voltage_Relays_Closed (out, see [2] Implausibilities[4B]), Precharge_Coil (in, see [2] Implausibilities[3B], [1] TSAL_Green[2A], [2] Implausibilities[1A], [3] Relay Implausibility[1A]), SC_End (in, see [2] Implausibilities[3B], [1] TSAL_Green[2B], [2] Implausibilities[1A], [3] Relay Implausibility[1B])

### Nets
+12: U401.14(VDD)
GND: R444.1 U401.7(VSS)
AIR+_Coil: U401.8(C) ; port AIR+_Coil
AIR-_Coil: U401.1(A) ; port AIR-_Coil
HV_Accumulator: U302.3(D) ; port HV_Accumulator
No_Voltage_Relays_Closed: R444.2 TP402.1(TP) U302.6(K) ; port No_Voltage_Relays_Closed
Not_Intentional_Relay_State: TP401.1(TP) U302.5(F) U401.9(J)
Precharge_Coil: U401.2(B) ; port Precharge_Coil
SC_End: U302.4(E) ; port SC_End

Not connected (* = marked no-connect by the designer): U401 3(D)* 4(E)* 5(F)* 6(K)* 10(L)* 11(I)* 12(H)* 13(G)*

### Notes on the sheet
- Inputs
- Outputs
- A plausibility check against the intentional state of the relays (AIRs + Precharge) inside the TSAC and the presence of HV in the Tractive System inside the TSAC is implemented on this sheet.
  When the intentional state of any relay is closed (Low Level), the Shutdown Chain is closed and there is no HV inside the TSAC, @{"Id":"EQTOHJWW\BLHVUNPR"} shifts to High Level.
  As the intentional state of the Relays is taken from the negative pole of the Relay's coil and all the coils of the Relays influencing the TS inside the TSAC are supplied directly from the SC, @{"Id":"MUSAZMGH\UPAUDIOF"} coinditions the output of @{"Id":"EQTOHJWW\BLHVUNPR"} in @{"Id":"OQJDTHJH\MDAINOXP"} .
- The table shown below reflects the Logic implemented in this sheet.

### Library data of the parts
*#5 = CMP-00043-7: Standard Title Block; .Creator: GP
R444 = CMP-00093-2: as R111 on sheet [1] TSAL_Green
TP401 TP402 = CMP-00042-1: Test Point 1x1 mm; .SCHcheck: GP
U302 = CMP-00213-1: as U101 on sheet [1] TSAL_Green
U401 = CMP-00215-1: NAND Gate, 4000/14000/40000 Series, 3-Func, 3-Input, CMOS, CDIP14; Min Supply Voltage: 5V; Package Body Material: Metal; Surface Mount: No; Number of Inputs: 3; Max Supply Voltage: 15V; Qualification Status: Not Qualified; Nominal Supply Voltage: 10V; Propagation Delay (tpd): 250ns

## Sheet [6] Green_Driver.SchDoc
size A4
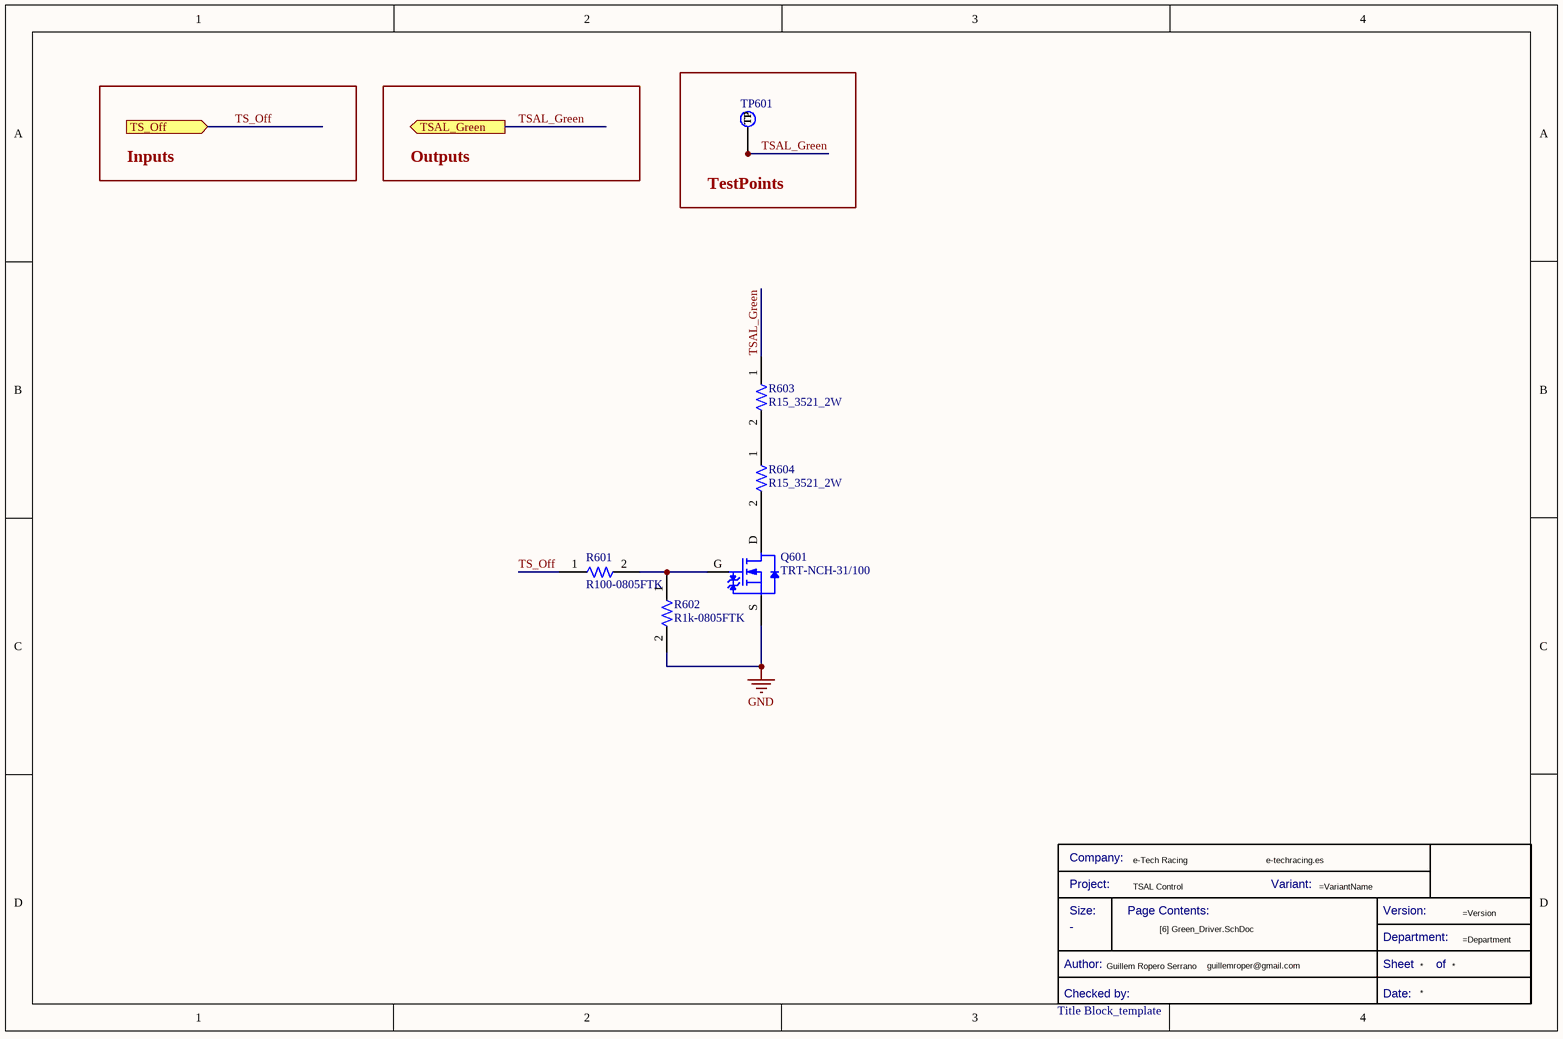
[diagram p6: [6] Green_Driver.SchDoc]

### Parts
(Parts that share a designator on the sheet are numbered #1, #2 ... from top to bottom, then left to right.)
*#6  Title Block_template  (graphical)
Q601  TRT-NCH-31/100  [TRT-NCH-D2PAK]
R601  R100-0805FTK  [R0805FTK]
R602  R1k-0805FTK  [R0805FTK]
R603  R15_3521_2W  [R_3521]
R604  R15_3521_2W  [R_3521]
TP601  TestPoint  [TestPoint]  (value not drawn)  (no BOM)

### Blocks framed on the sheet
TestPoints: TP601

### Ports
TS_Off (in, see [1] TSAL_Green[1D], [1] TSAL_Green[3A]), TSAL_Green (out, see [1] TSAL_Green[2D], [1] TSAL_Green[3A])

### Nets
GND: Q601.S R602.2
TS_Off: R601.1 ; port TS_Off
TSAL_Green: R603.1 TP601.1(TP) ; port TSAL_Green
NetQ601_D: Q601.D R604.2
NetQ601_G: Q601.G R601.2 R602.1
NetR603_2: R603.2 R604.1

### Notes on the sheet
- Inputs
- Outputs

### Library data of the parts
*#6 = CMP-00043-7: Standard Title Block; .Creator: GP
Q601 = CMP-00139-1: MOSFET N-CH 100V 31A DPAK; Manufacturer 1: Infineon; Manufacturer Part Number 1: IRFR3410TRPBF; Rds On Max: 39mR; Turn-On Delay Time: 12ns; Polarization: N; Threshold Voltage: 4V; Power Dissipation: 110W; Input Capacitance: 1.69nF; Max Power Dissipation: 3W; Gate to Source Voltage (Vgs): 20V; Turn-Off Delay Time: 40ns
R601 = CMP-00083-2: Res Thick Film 0805 100 Ohm 1% 1/8W ±100ppm/°C Molded SMD SMD Paper Tape on Plastic Reel; Manufacturer Part Number 1: CR0805-FX-1000ELF; Manufacturer 1: Bourns; Power Rating: 125mW; Voltage Rating (DC): 150V; .Creator: DR; Value: 100
R602 = CMP-00076-2: as R501 on sheet [5] SCS
R603 R604 = CMP-00075-6: Res Thick Film 2512 15 Ohm 1% 2W ±100ppm/C Pad SMD T/R; Manufacturer Part Number 1: 352115RFT; Manufacturer 1: TE Connectivity; Value: 15; .Creator: DR; Voltage Rating: 250V; Temperature Coefficient: 100ppm/°C; Number of Resistors: 1
TP601 = CMP-00042-1: Test Point 1x1 mm; .SCHcheck: GP

## Sheet [7] TSAL_Red.SchDoc
size A4
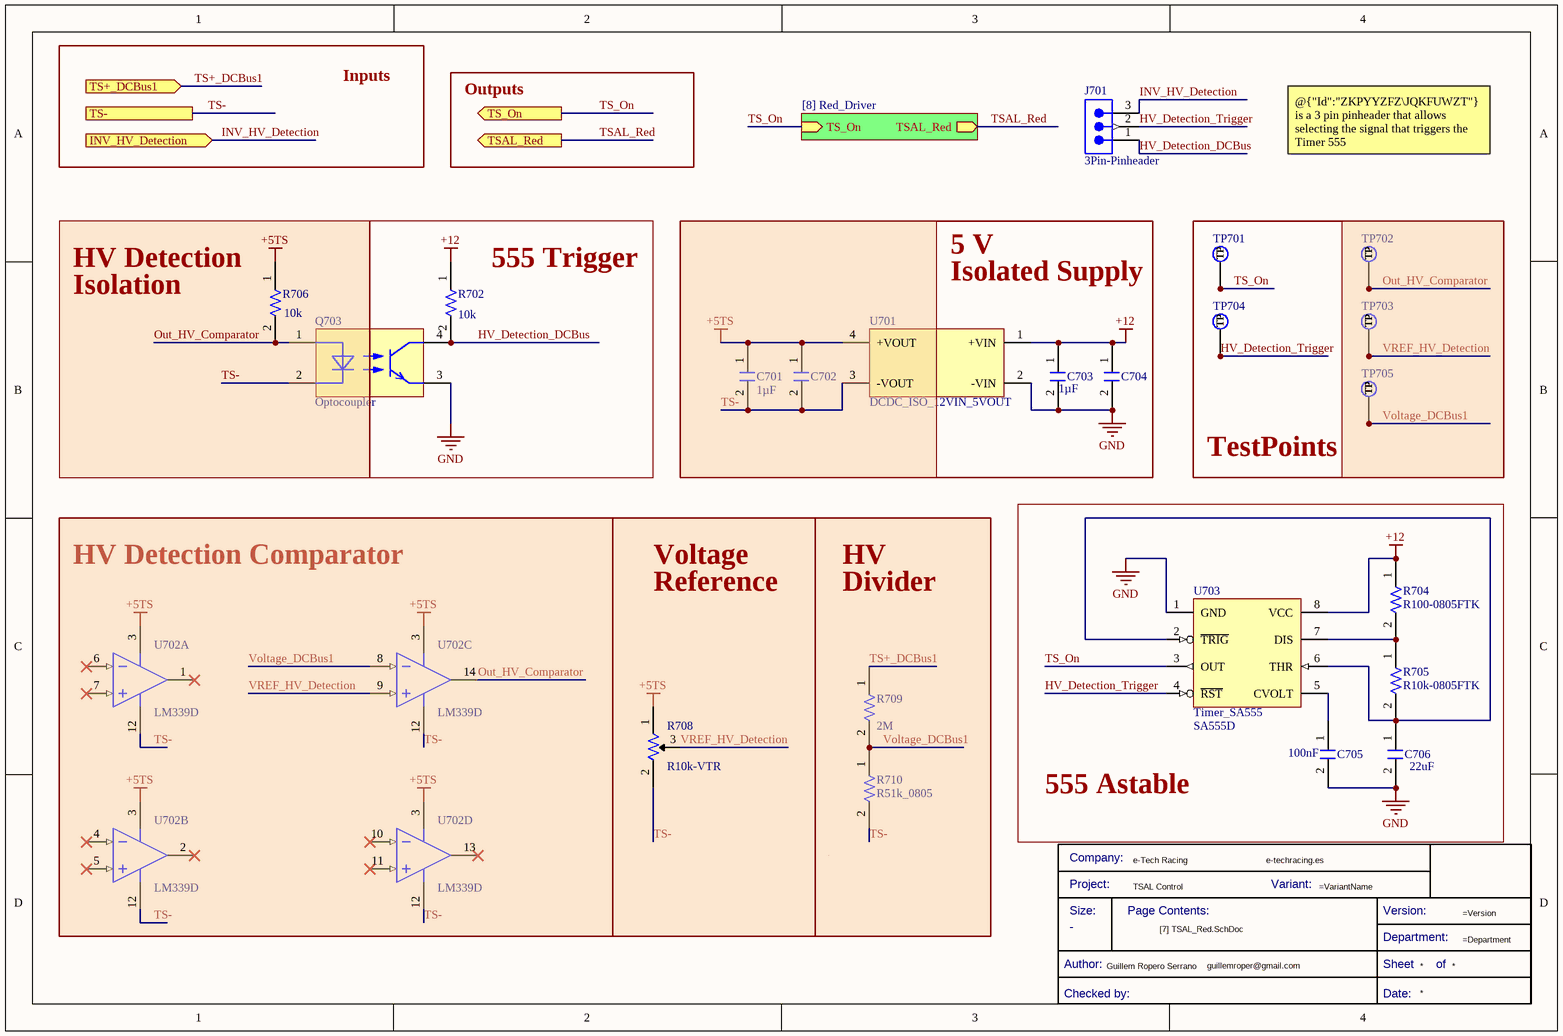
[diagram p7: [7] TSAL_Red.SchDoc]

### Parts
(Parts that share a designator on the sheet are numbered #1, #2 ... from top to bottom, then left to right.)
*#7  Title Block_template  (value not drawn)  (graphical)
C701  value 1µF  [C0805FNPC-R]  (hidden comment: C1u-50V-0805FNPC-X7R)
C702  C100n-16V-0805  [WCAP-CSGP_0805_L2W1.25H0.8_Reflow]  (value not drawn)
C703  value 1µF  [C0805FNPC-R]  (hidden comment: C1u-50V-0805FNPC-X7R)
C704  C100n-16V-0805  [WCAP-CSGP_0805_L2W1.25H0.8_Reflow]  (value not drawn)
C705  value 100nF  [WCAP-CSGP_0805_L2W1.25H0.8_Reflow]  (hidden comment: C100n-16V-0805)
C706  value 22uF  [WCAP-CSGP_0805_L2W1.25H0.8_Reflow]  (hidden comment: C22u-25V-0805)
J701  3Pin-Pinheader  [61300311121]
Q703  Optocoupler  [WL-OCPT_LSOP4]
R702  value 10k  [R0805FTK]  (hidden comment: R10k-0805FTK)
R704  R100-0805FTK  [R0805FTK]
R705  R10k-0805FTK  [R0805FTK]
R706  value 10k  [R0805FTK]  (hidden comment: R10k-0805FTK)
R708  R10k-VTR  [R10k-VTR]
R709  Resistance: 2M  [R2512FTK]  (hidden comment: R2M-2512FTK)
R710  R51k_0805  [0805]
TP701  TestPoint  [TestPoint]  (value not drawn)  (no BOM)
TP702  TestPoint  [TestPoint]  (value not drawn)  (no BOM)
TP703  TestPoint  [TestPoint]  (value not drawn)  (no BOM)
TP704  TestPoint  [TestPoint]  (value not drawn)  (no BOM)
TP705  TestPoint  [TestPoint]  (value not drawn)  (no BOM)
U701  DCDC_ISO_12VIN_5VOUT  [WPME-FISM_SIP-7_L19.65W7.05H10.16]
U702  LM339D  [D0014A_N]  (parts A,B,C,D of 4)
U703  Timer_SA555  Manufacturer Part Number: SA555D  [Timer_SA555]

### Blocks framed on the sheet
555 Trigger: Q703 R702
TestPoints: TP701-TP705
HV Detection Comparator: U702
555 Astable: C705 C706 R704 R705 U703

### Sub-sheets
Red Driver = [8] Red_Driver: TS_On (in), TSAL_Red (out)

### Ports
INV_HV_Detection (in, see TSAL_Control[1C]), TS+_DCBus1 (in, see TSAL_Control[1C]), TS- (see TSAL_Control[1C]), TS_On (out, see TSAL_Control[2C], [8] Red_Driver[1A]), TSAL_Red (out, see TSAL_Control[2C], [8] Red_Driver[1A])

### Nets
+5TS: C701.1 C702.1 R706.1 R708.1 U701.4(+VOUT) U702.3(VCC)
+12: C703.1 C704.1 R702.1 R704.1 U701.1(+VIN) U703.8(VCC)
GND: C703.2 C704.2 C705.2 C706.2 Q703.3(Emitter) U701.2(-VIN) U703.1(GND)
HV_Detection_DCBus: J701.1 Q703.4(Collector) R702.2
HV_Detection_Trigger: J701.2 TP704.1(TP) U703.4(~{RST})
INV_HV_Detection: J701.3 ; port INV_HV_Detection
Out_HV_Comparator: Q703.1(Anode) R706.2 TP702.1(TP) U702.14(OUT3)
TS+_DCBus1: R709.1 ; port TS+_DCBus1
TS-: C701.2 C702.2 Q703.2(Cathode) R708.2 R710.2 U701.3(-VOUT) U702.12(GND) ; port TS-
TS_On: TP701.1(TP) U703.3(OUT) ; port TS_On, sheet Red Driver/TS_On
TSAL_Red: port TSAL_Red, sheet Red Driver/TSAL_Red
Voltage_DCBus1: R709.2 R710.1 TP705.1(TP) U702.8(IN3-)
VREF_HV_Detection: R708.3 TP703.1(TP) U702.9(IN3+)
NetC705_1: C705.1 U703.5(CVOLT)
NetC706_1: C706.1 R705.2 U703.2(~{TRIG}) U703.6(THR)
NetR704_2: R704.2 R705.1 U703.7(DIS)

Not connected (* = marked no-connect by the designer): U702 1(OUT1)* 2(OUT2)* 4(IN2-)* 5(IN2+)* 6(IN1-)* 7(IN1+)* 10(IN4-)* 11(IN4+)* 13(OUT4)*

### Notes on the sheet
- Inputs
- Outputs
- @{"Id":"ZKPYYZFZ\JQKFUWZT"} is a 3 pin pinheader that allows selecting the signal that triggers the Timer 555 @{"Id":"ZKPYYZFZ\MNTXXXUA"} to oscillate and drive the TSAL Red.
- (near R706) HV Detection
- Isolation
- 5 V
- Isolated Supply
- Voltage
- HV
- Reference
- Divider

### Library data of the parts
*#7 = CMP-00043-7: Standard Title Block; .Creator: GP
C701 C703 = CMP-00052-2: Multilayer Ceramic Capacitor, Wcap-Csgp Series, 1 F, 10%, X7R, 50 V, 0805 [2012 Metric] Rohs Compliant: Yes; Manufacturer Part Number 1: 885012207103; Manufacturer 1: Wurth Electronics; Voltage Rating (DC): 50V; .Creator: GP
C702 C704 C705 = CMP-001-00008-6: Ceramic Capacitor, Multilayer, Ceramic, 16V, 10% +Tol, 10% -Tol, X7R, 15% TC, 0.1uF, Surface Mount, 0805
C706 = CMP-001-00017-4: 885012107019
J701 = CMP-002-00009-1: Board Connector, 3 Contact(s), 1 Row(s), Male, Straight, 0.1 inch Pitch, Solder Terminal, Locking, Black Insulator, Plug
Q703 = CMP-00195-1: Transistor Output Optocoupler. S/N: 140100146000
R702 R706 = CMP-00085-4: as R201 on sheet [2] Implausibilities
R704 = CMP-00083-2: as R601 on sheet [6] Green_Driver
R705 = CMP-00085-4: BOURNS         CR0805-JW-103ELF            Surface Mount Chip Resistor, Thick Film, CR Series, 10 kohm, 125 mW,  5%, 150 V; .Creator: DR; Power Rating: 125mW; Voltage Rating (DC): 100V; Voltage Rating: 150V; Temperature Coefficient: 200ppm/°C; Value: 10k
R708 = CMP-00072-1: Trimmer, Cermet, Rest 10 Kilohms, PCB, 25 Turns, Pwr-Rtg 0.5W, 3296 Series; Manufacturer Part Number: 3296W-1-103LF; Manufacturer: Bourns; Insulation Resistance: 1GR; Max Power Dissipation: 500mW; .Creator: DO; Tolerance: 10%; Value: 10k; Number of Turns: 25; Temperature Coefficient: 100ppm/°C
R709 = CMP-00108-2: Current Sense Resistors - SMD 3watts .002ohms 1%; Manufacturer: Vishay Dale; Manufacturer Part Number: WSLP25122L000FEA; Power Rating: 3W; Temperature Coefficient: 275ppm/°C
R710 = CMP-009-00018-4: Fixed Resistor, Metal Glaze/thick Film, 0.125W, 51000ohm, 150V, 1% +/-Tol, 100ppm/Cel, Surface Mount, 0805. ERJ-6ENF5102V; Power: 125mW; Value: 51k
TP701-TP705 = CMP-00042-1: Test Point 1x1 mm; .SCHcheck: GP
U701 = CMP-019-00001-1: WPME-FISM Fixed Isolated SIP/SMT Module
U702 = CMP-014-00006-1: as U501 on sheet [5] SCS
U703 = CMP-00181-3: Precision timer for -55 to 85C operation 8-SOIC -40 to 85; Manufacturer: Texas Instruments; Max Supply Voltage: 16V; Quiescent Current: 15mA; Min Supply Voltage: 4.5V; Low Level Output Current: 200mA; Frequency: 500kHz; Nominal Supply Current: 2mA; Number of Timers/Counters: 1; .Creator: DO; Operating Supply Current: 10mA; High Level Output Current: -200mA

## Sheet [8] Red_Driver.SchDoc
size A4
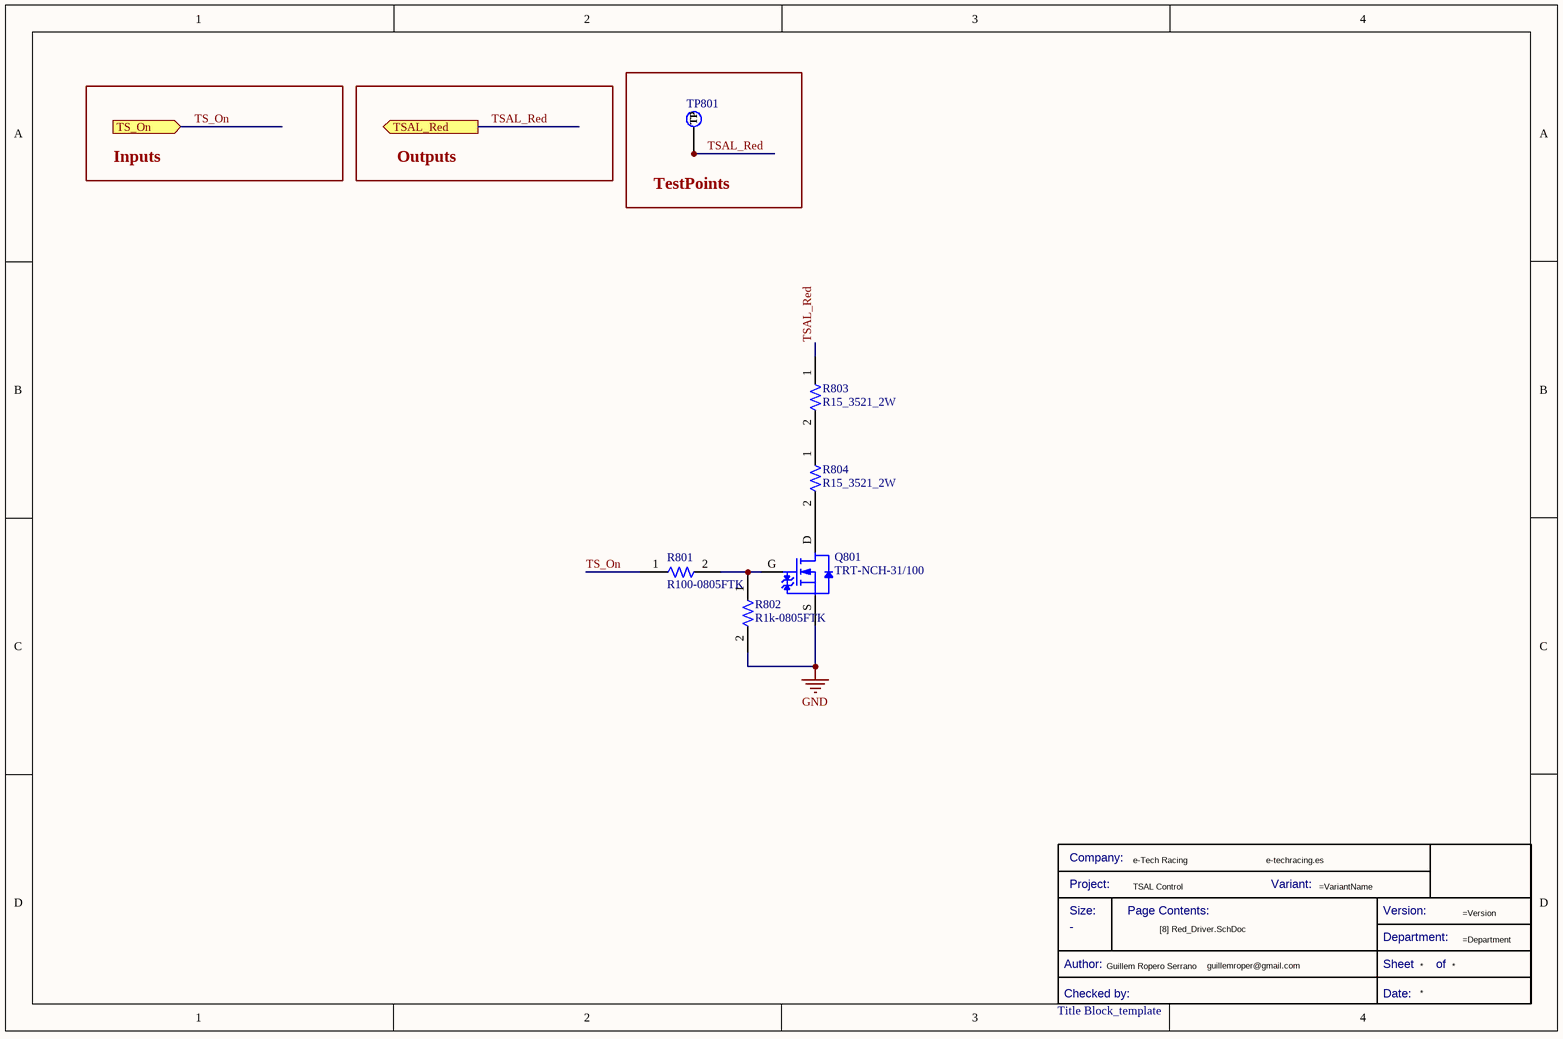
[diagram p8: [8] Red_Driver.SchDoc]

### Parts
(Parts that share a designator on the sheet are numbered #1, #2 ... from top to bottom, then left to right.)
*#8  Title Block_template  (graphical)
Q801  TRT-NCH-31/100  [TRT-NCH-D2PAK]
R801  R100-0805FTK  [R0805FTK]
R802  R1k-0805FTK  [R0805FTK]
R803  R15_3521_2W  [R_3521]
R804  R15_3521_2W  [R_3521]
TP801  TestPoint  [TestPoint]  (value not drawn)  (no BOM)

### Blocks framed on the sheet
TestPoints: TP801

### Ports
TS_On (in, see [7] TSAL_Red[3A], [7] TSAL_Red[2A]), TSAL_Red (out, see [7] TSAL_Red[3A], [7] TSAL_Red[2A])

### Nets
GND: Q801.S R802.2
TS_On: R801.1 ; port TS_On
TSAL_Red: R803.1 TP801.1(TP) ; port TSAL_Red
NetQ801_D: Q801.D R804.2
NetQ801_G: Q801.G R801.2 R802.1
NetR803_2: R803.2 R804.1

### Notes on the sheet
- Inputs
- Outputs

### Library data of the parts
*#8 = CMP-00043-7: Standard Title Block; .Creator: GP
Q801 = CMP-00139-1: as Q601 on sheet [6] Green_Driver
R801 = CMP-00083-2: as R601 on sheet [6] Green_Driver
R802 = CMP-00076-2: as R501 on sheet [5] SCS
R803 R804 = CMP-00075-6: as R603 on sheet [6] Green_Driver
TP801 = CMP-00042-1: Test Point 1x1 mm; .SCHcheck: GP

## Sheet [9] Discharge_Circuit.SchDoc
size A4
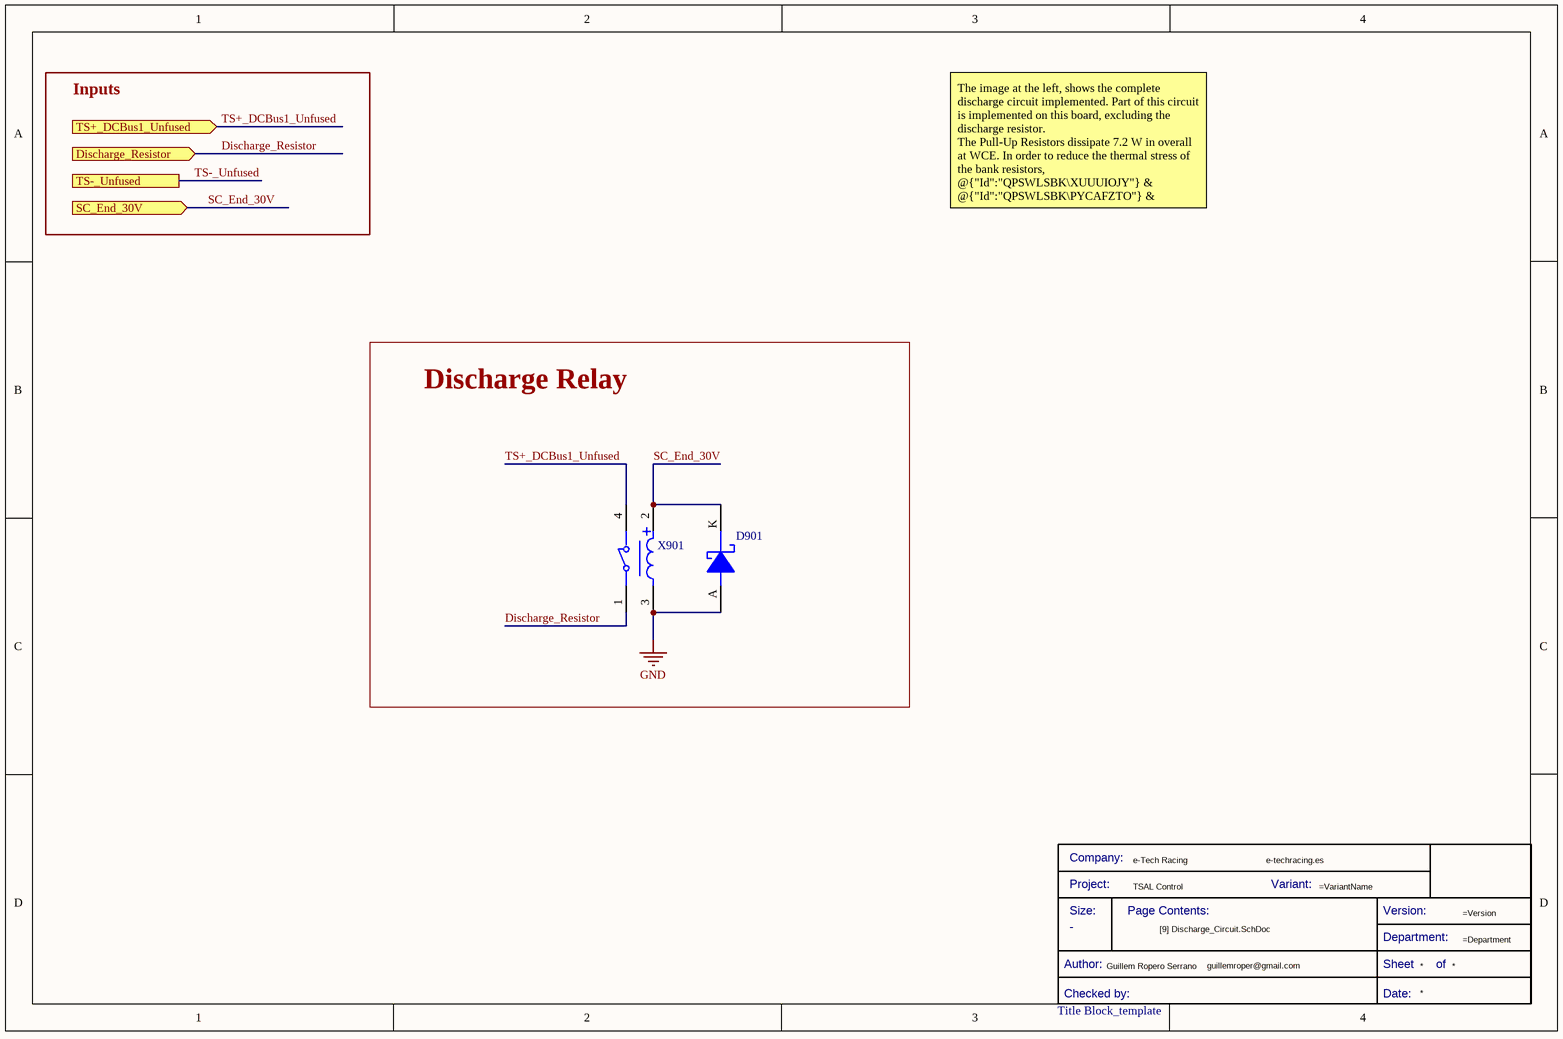
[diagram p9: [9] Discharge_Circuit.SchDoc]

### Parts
(Parts that share a designator on the sheet are numbered #1, #2 ... from top to bottom, then left to right.)
*#9  Title Block_template  (graphical)
D901  DSC-0.5/30-SOD123  [DSC-SOD123]  (value not drawn)
X901  HV-Relay-SPST-NC-24V  [HV-Relay-SPST-NC-24V]  (value not drawn)

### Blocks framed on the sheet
Discharge Relay: D901 X901

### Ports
Discharge_Resistor (in, see TSAL_Control[1D]), SC_End_30V (in, see TSAL_Control[1D]), TS+_DCBus1_Unfused (in, see TSAL_Control[1C]), TS-_Unfused (see TSAL_Control[1D])

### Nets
GND: D901.A X901.3
Discharge_Resistor: X901.1 ; port Discharge_Resistor
SC_End_30V: D901.K X901.2 ; port SC_End_30V
TS+_DCBus1_Unfused: X901.4 ; port TS+_DCBus1_Unfused

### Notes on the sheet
- Inputs
- The image at the left, shows the complete discharge circuit implemented. Part of this circuit is implemented on this board, excluding the discharge resistor.
  The Pull-Up Resistors dissipate 7.2 W in overall at WCE. In order to reduce the thermal stress of the bank resistors, @{"Id":"QPSWLSBK\XUUUIOJY"} & @{"Id":"QPSWLSBK\PYCAFZTO"} & @{"Id":"QPSWLSBK\KMQGLCTP"} & @{"Id":"QPSWLSBK\MRRGDNMJ"} are 3W rated and dissipate 1.8 W in WCE each one.

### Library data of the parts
*#9 = CMP-00043-7: Standard Title Block; .Creator: GP
D901 = CMP-00165-2: VR=30V IF=500mA 30pF P=410mW; Peak Non-Repetitive Surge Current: 5.5A; .Creator: GP; Voltage Rating (DC): 30V; Current Rating: 500mA; Max Reverse Leakage Current: 130uA; Element Configuration: Single; Polarity: Standard; Forward Voltage: 430mV
X901 = CMP-00224-2: Dry Reed Relay, SPST-NC, 3500V switching voltage, 3A, 10kV isolation coil-contacts, 5504-24-1

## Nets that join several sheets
+12: TSAL_Control (5 pins), [1] TSAL_Green (R111.2 U101.14), [2] Implausibilities (Q202.G R202.1 U201.14 U202.14), [3] Relay Implausibility (U301.14 U302.1 U302.14), [5] SCS (7 pins), [4] NoHV_RelaysClosed (U401.14), [7] TSAL_Red (6 pins)
GND: TSAL_Control (18 pins), [1] TSAL_Green (U101.7), [2] Implausibilities (7 pins), [3] Relay Implausibility (R333.1 U201.12 U301.7 U302.7), [5] SCS (R505.2 R555.1 U501.12 U502.7), [4] NoHV_RelaysClosed (R444.1 U401.7), [6] Green_Driver (Q601.S R602.2), [7] TSAL_Red (7 pins), [8] Red_Driver (Q801.S R802.2), [9] Discharge_Circuit (D901.A X901.3)
AIR+_Coil: TSAL_Control (R3.2 R4.1), [1] TSAL_Green (TP106.1), [3] Relay Implausibility (U301.1), [4] NoHV_RelaysClosed (U401.8)
AIR+_State: TSAL_Control (J1.1), [1] TSAL_Green (TP102.1 U101.1), [3] Relay Implausibility (U301.2), [5] SCS (U501.11)
AIR-_Coil: TSAL_Control (R5.2 R6.1), [1] TSAL_Green (TP108.1), [3] Relay Implausibility (U301.5), [4] NoHV_RelaysClosed (U401.1)
AIR-_State: TSAL_Control (J1.2), [1] TSAL_Green (TP104.1 U101.2), [3] Relay Implausibility (U301.6), [5] SCS (U501.7)
Discharge_Resistor: TSAL_Control (J2.1 J2.2), [9] Discharge_Circuit (X901.1)
HV_Accumulator: TSAL_Control (J1.4), [1] TSAL_Green (TP105.1 U101.8), [5] SCS (U501.9), [4] NoHV_RelaysClosed (U302.3)
INV_HV_Detection: TSAL_Control (Q1.D R1.2), [7] TSAL_Red (J701.3)
No_Voltage_Relays_Closed: [2] Implausibilities (U201.3), [4] NoHV_RelaysClosed (R444.2 TP402.1 U302.6)
Precharge_Coil: TSAL_Control (R7.2 R8.1), [1] TSAL_Green (TP107.1), [3] Relay Implausibility (U301.9), [4] NoHV_RelaysClosed (U401.2)
Precharge_State: TSAL_Control (J1.3), [1] TSAL_Green (TP103.1 U101.3), [3] Relay Implausibility (U301.8), [5] SCS (U501.5)
Relays_Implausibility: [2] Implausibilities (U201.2), [3] Relay Implausibility (R333.2 TP305.1 U302.9)
Safe_State: [1] TSAL_Green (R111.1 U101.5), [2] Implausibilities (TP204.1 U202.9 U202.11)
SC_End: TSAL_Control (R9.2 R10.1), [1] TSAL_Green (TP109.1), [3] Relay Implausibility (U302.2), [4] NoHV_RelaysClosed (U302.4)
SC_End_30V: TSAL_Control (J1.13 J6.2 R9.1), [9] Discharge_Circuit (D901.K X901.2)
SCS_Error: [2] Implausibilities (U201.4), [5] SCS (R555.2 TP506.1 U502.1)
TS+_DCBus1: TSAL_Control (F3.1), [7] TSAL_Red (R709.1)
TS+_DCBus1_Unfused: TSAL_Control (F3.2 J3.1 J3.2), [9] Discharge_Circuit (X901.4)
TS-: TSAL_Control (F4.1), [7] TSAL_Red (7 pins)
TS_Off: TSAL_Control (J1.5), [1] TSAL_Green (TP101.1 U101.6), [6] Green_Driver (R601.1)
TS_On: TSAL_Control (J1.15), [7] TSAL_Red (TP701.1 U703.3), [8] Red_Driver (R801.1)
TSAL_Green: TSAL_Control (J1.9), [6] Green_Driver (R603.1 TP601.1)
TSAL_Red: TSAL_Control (J1.14), [8] Red_Driver (R803.1 TP801.1)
